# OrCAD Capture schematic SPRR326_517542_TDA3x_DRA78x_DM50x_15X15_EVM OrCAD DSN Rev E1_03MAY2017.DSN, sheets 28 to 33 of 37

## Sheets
28 SH36 - TOOL HPC: size C; rev: A
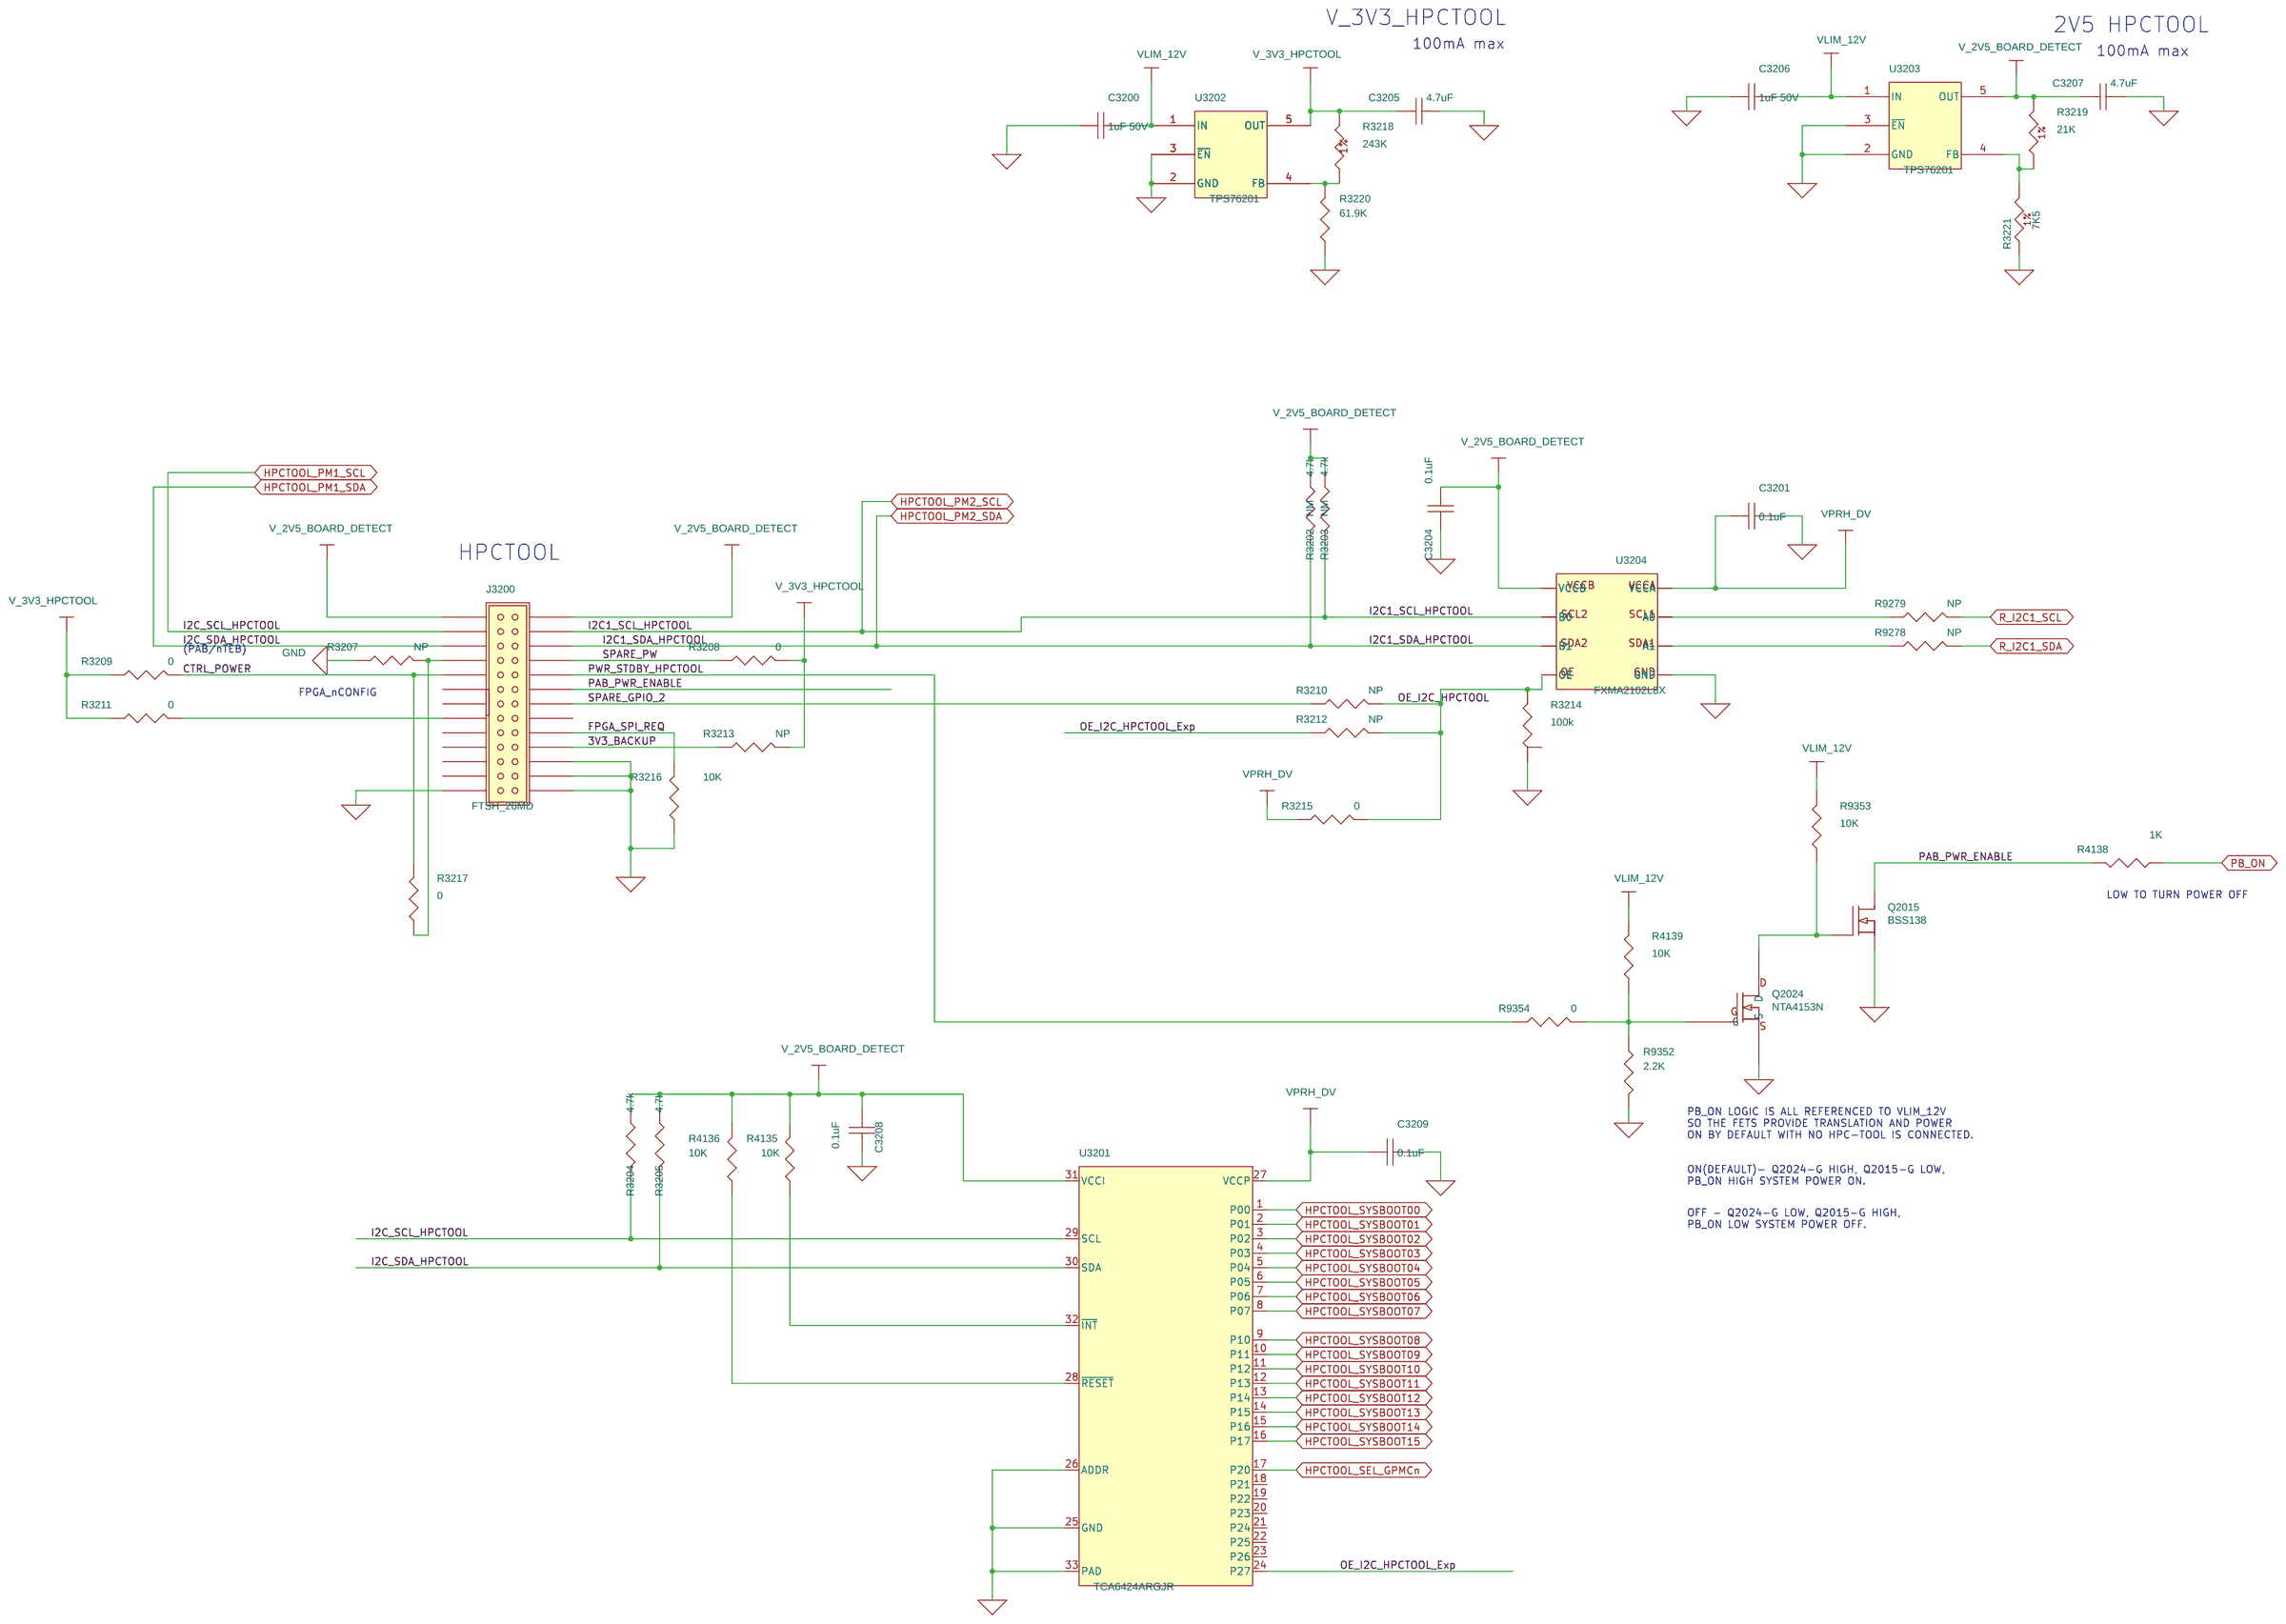
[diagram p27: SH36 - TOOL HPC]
29 SH37 - TOOL POWER MONITOR: size C; rev: E
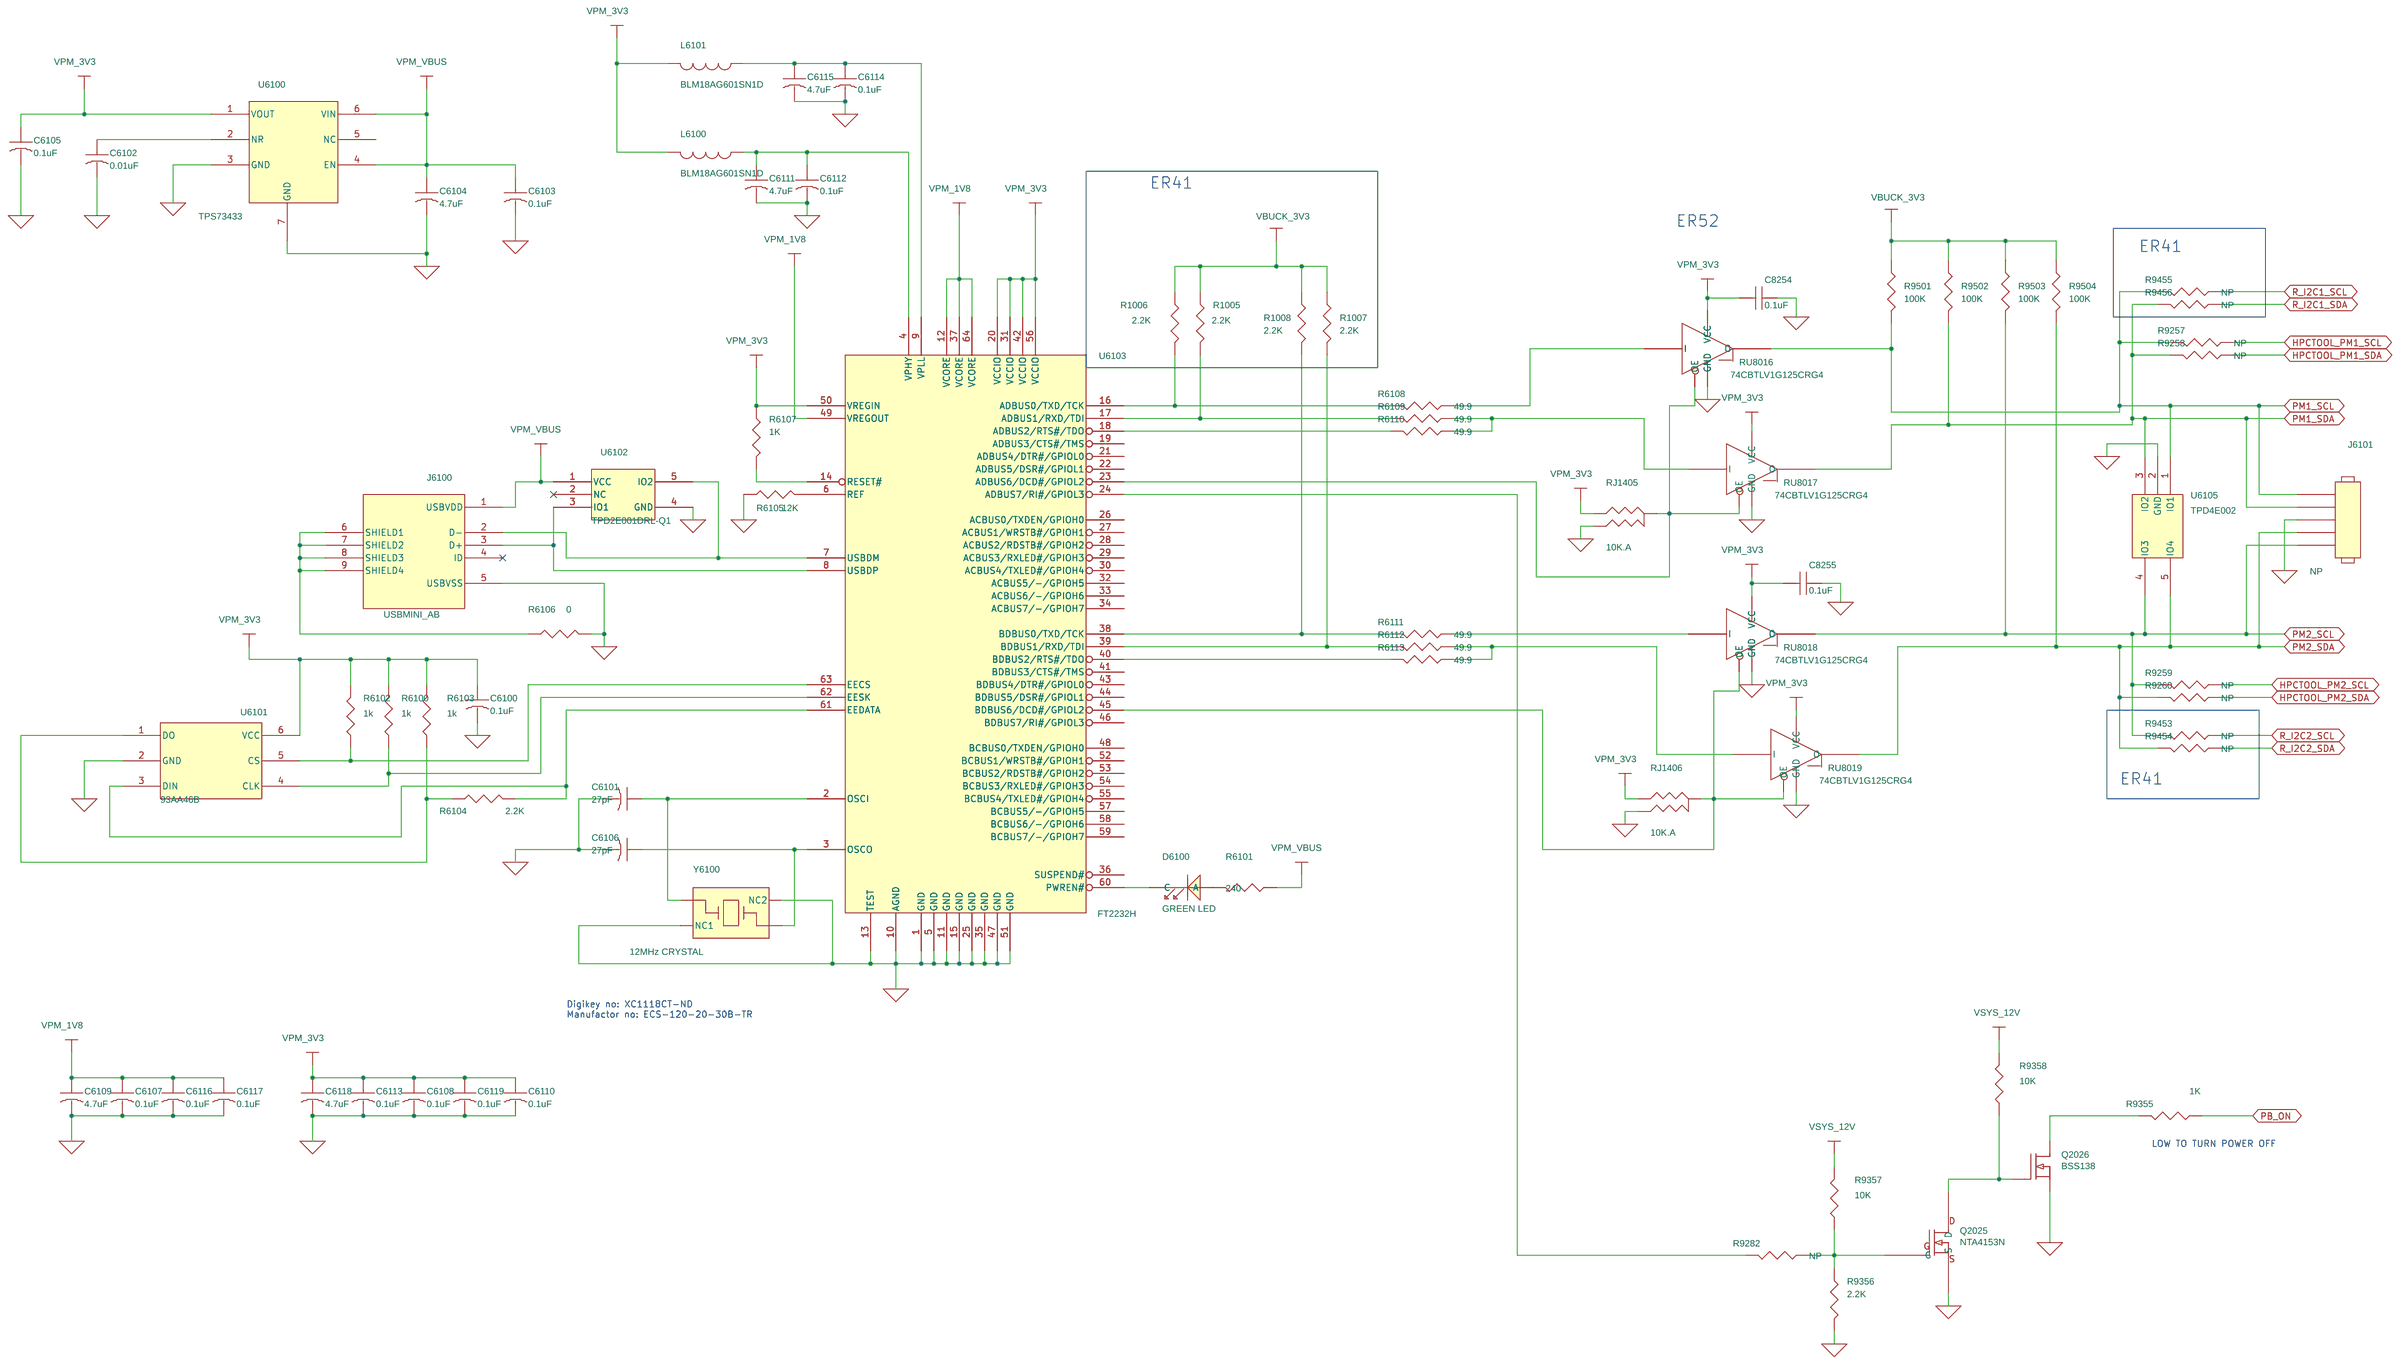
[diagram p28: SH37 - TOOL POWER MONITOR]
30 SH11 - MUX A/B/C: size C; rev: A
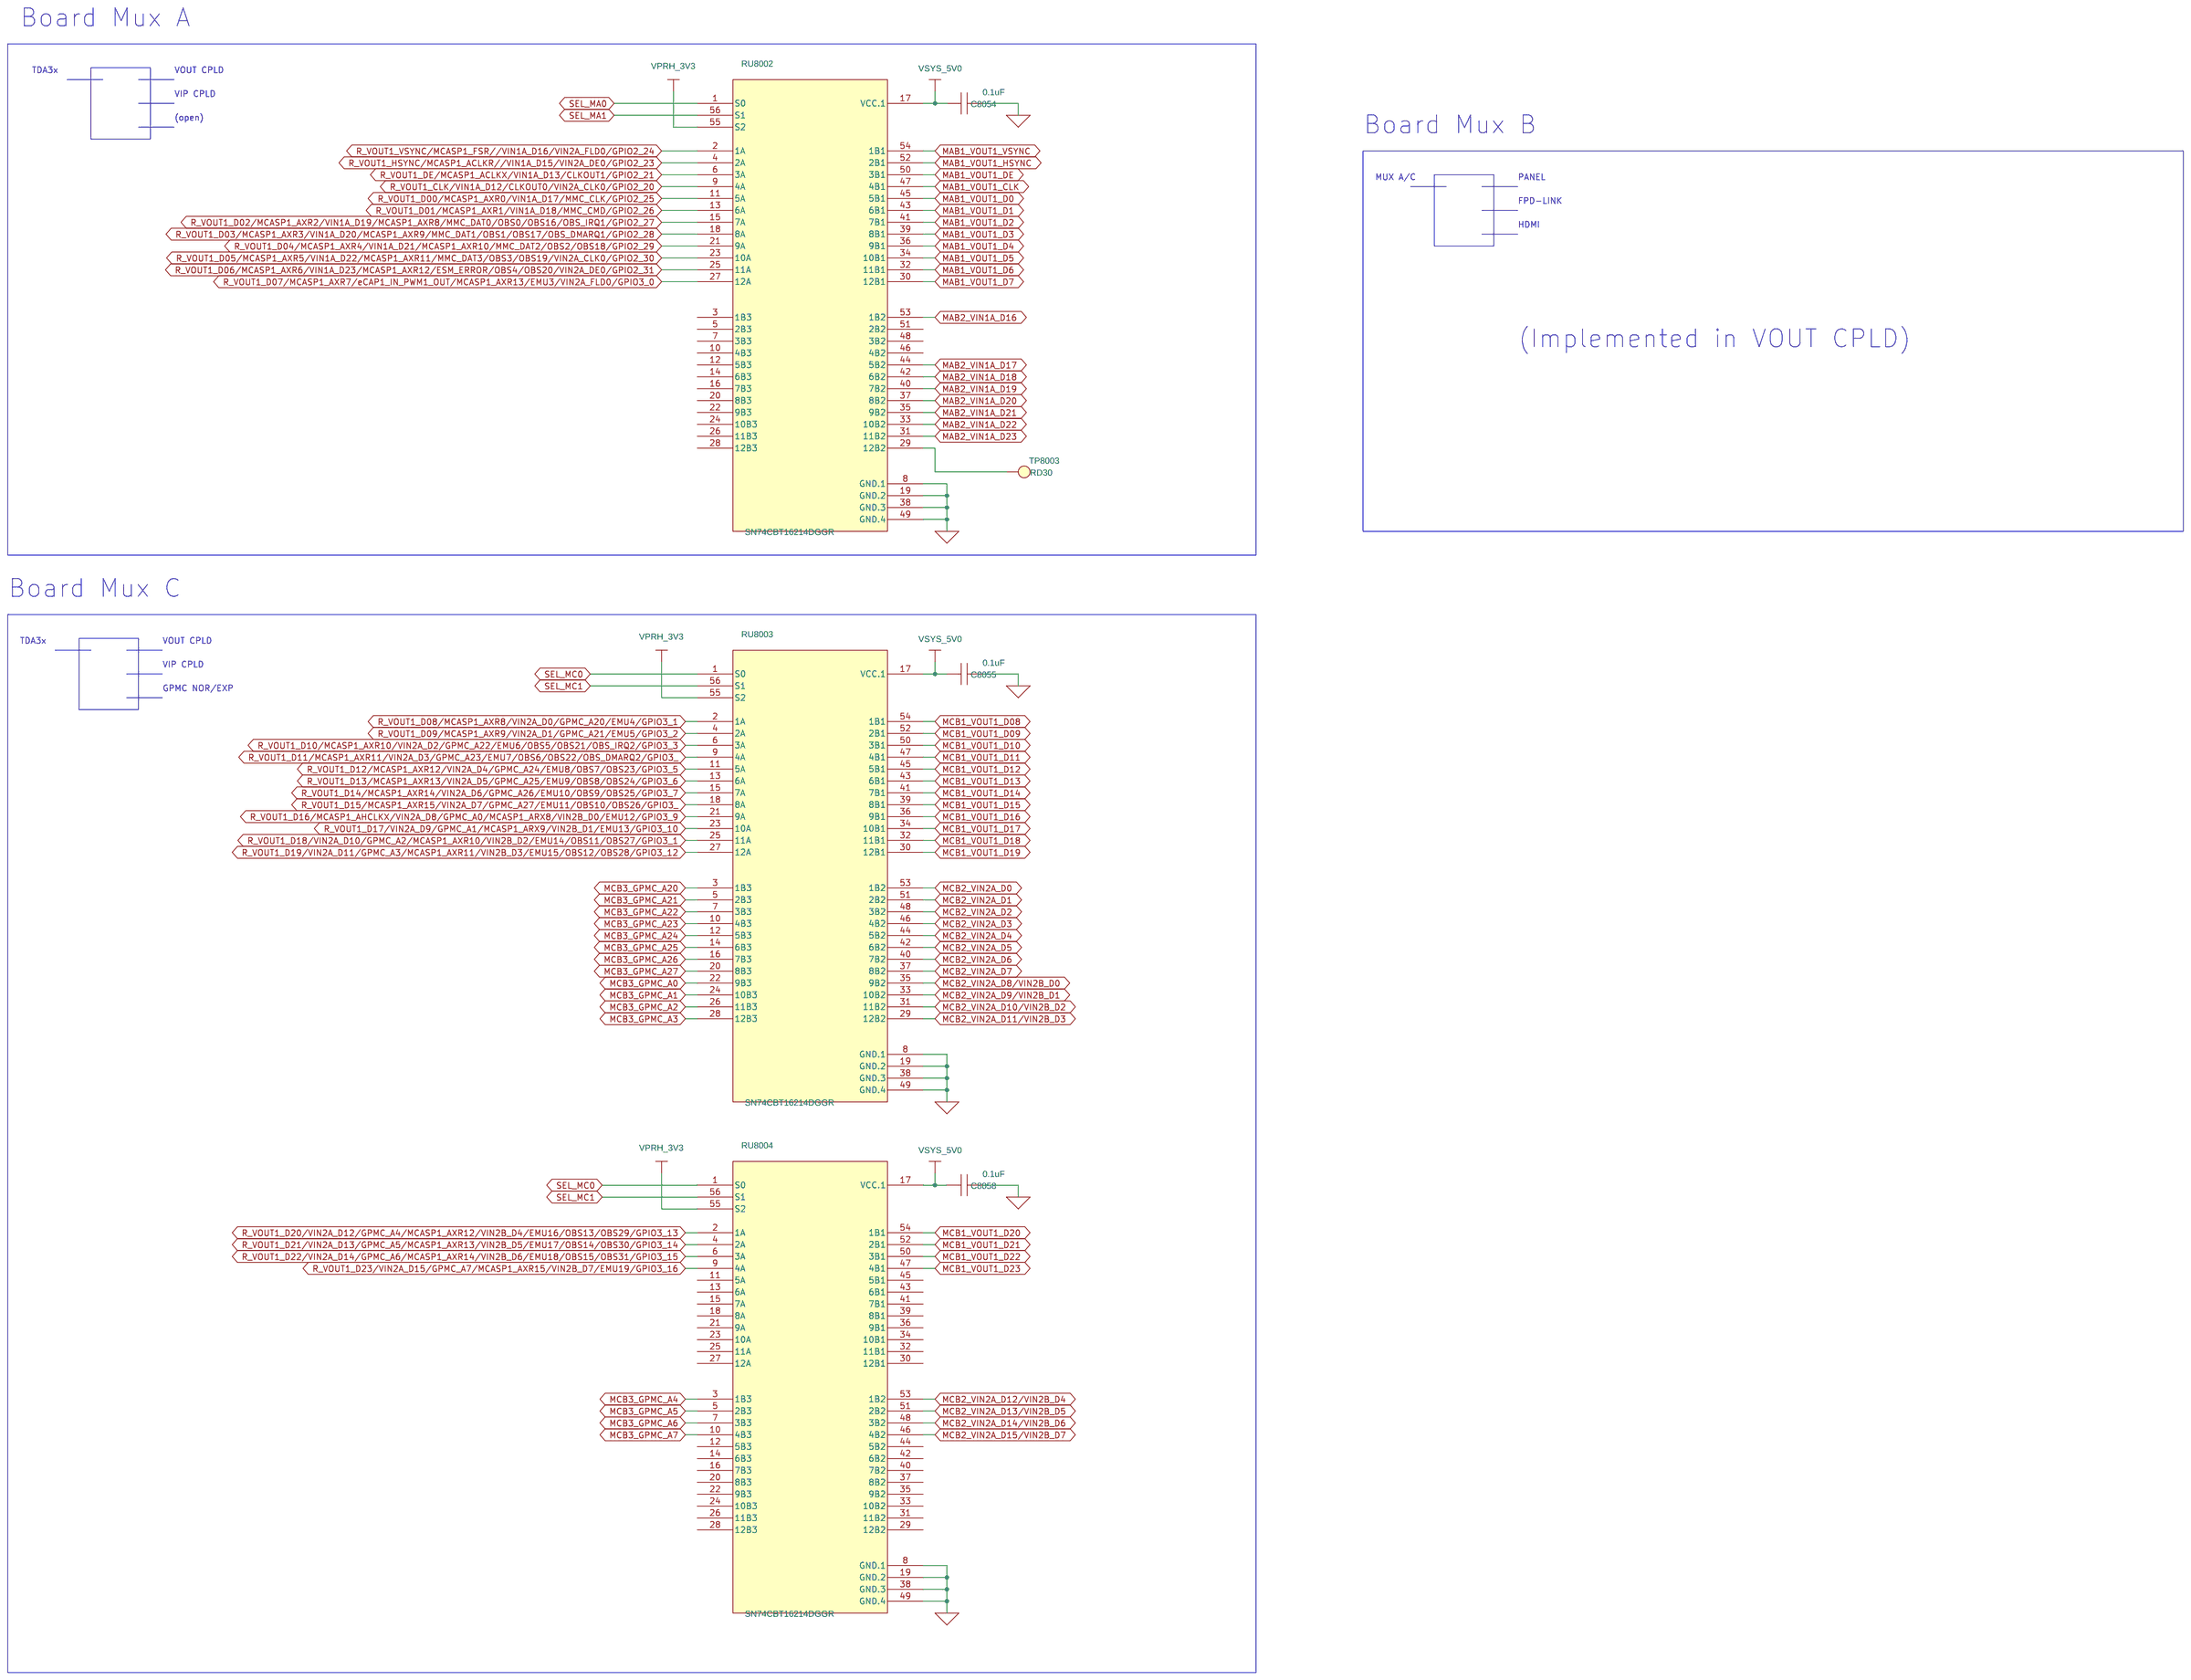
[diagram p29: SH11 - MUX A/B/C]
31 SH09 - BOOT/JTAG: size C; rev: D
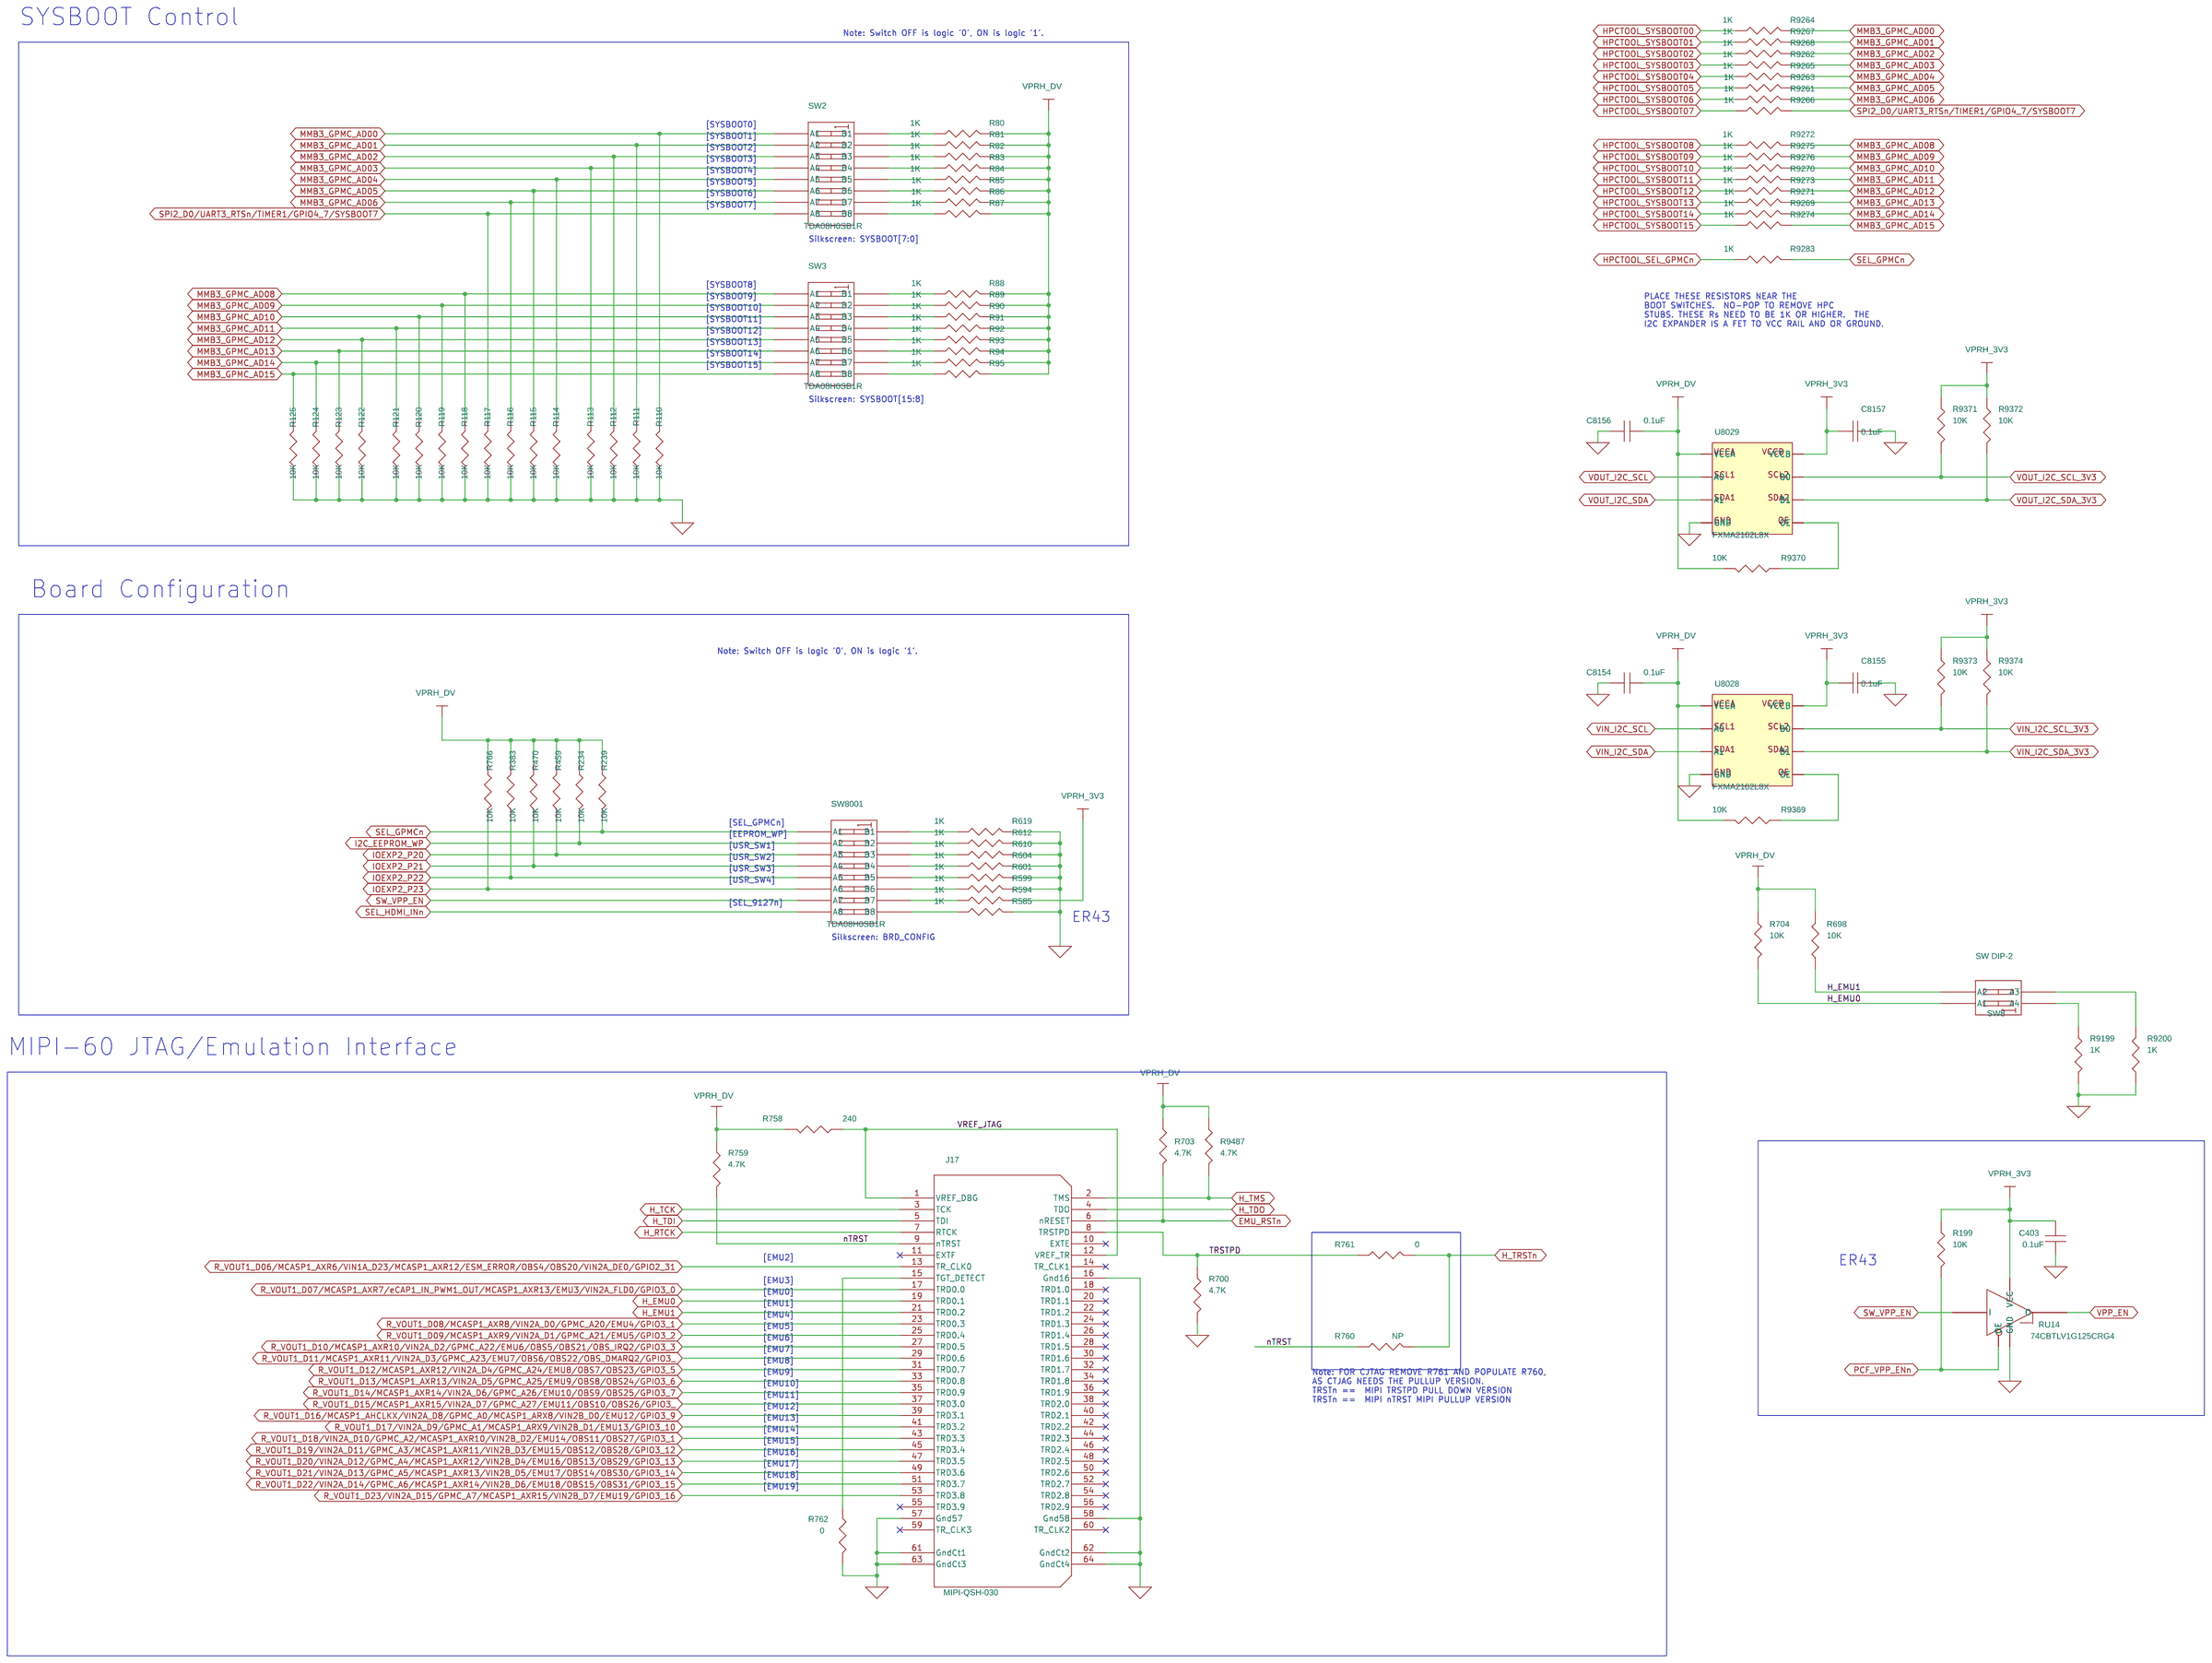
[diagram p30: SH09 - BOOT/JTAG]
32 SH13 - MUX J/K/M/N: size C; rev: B
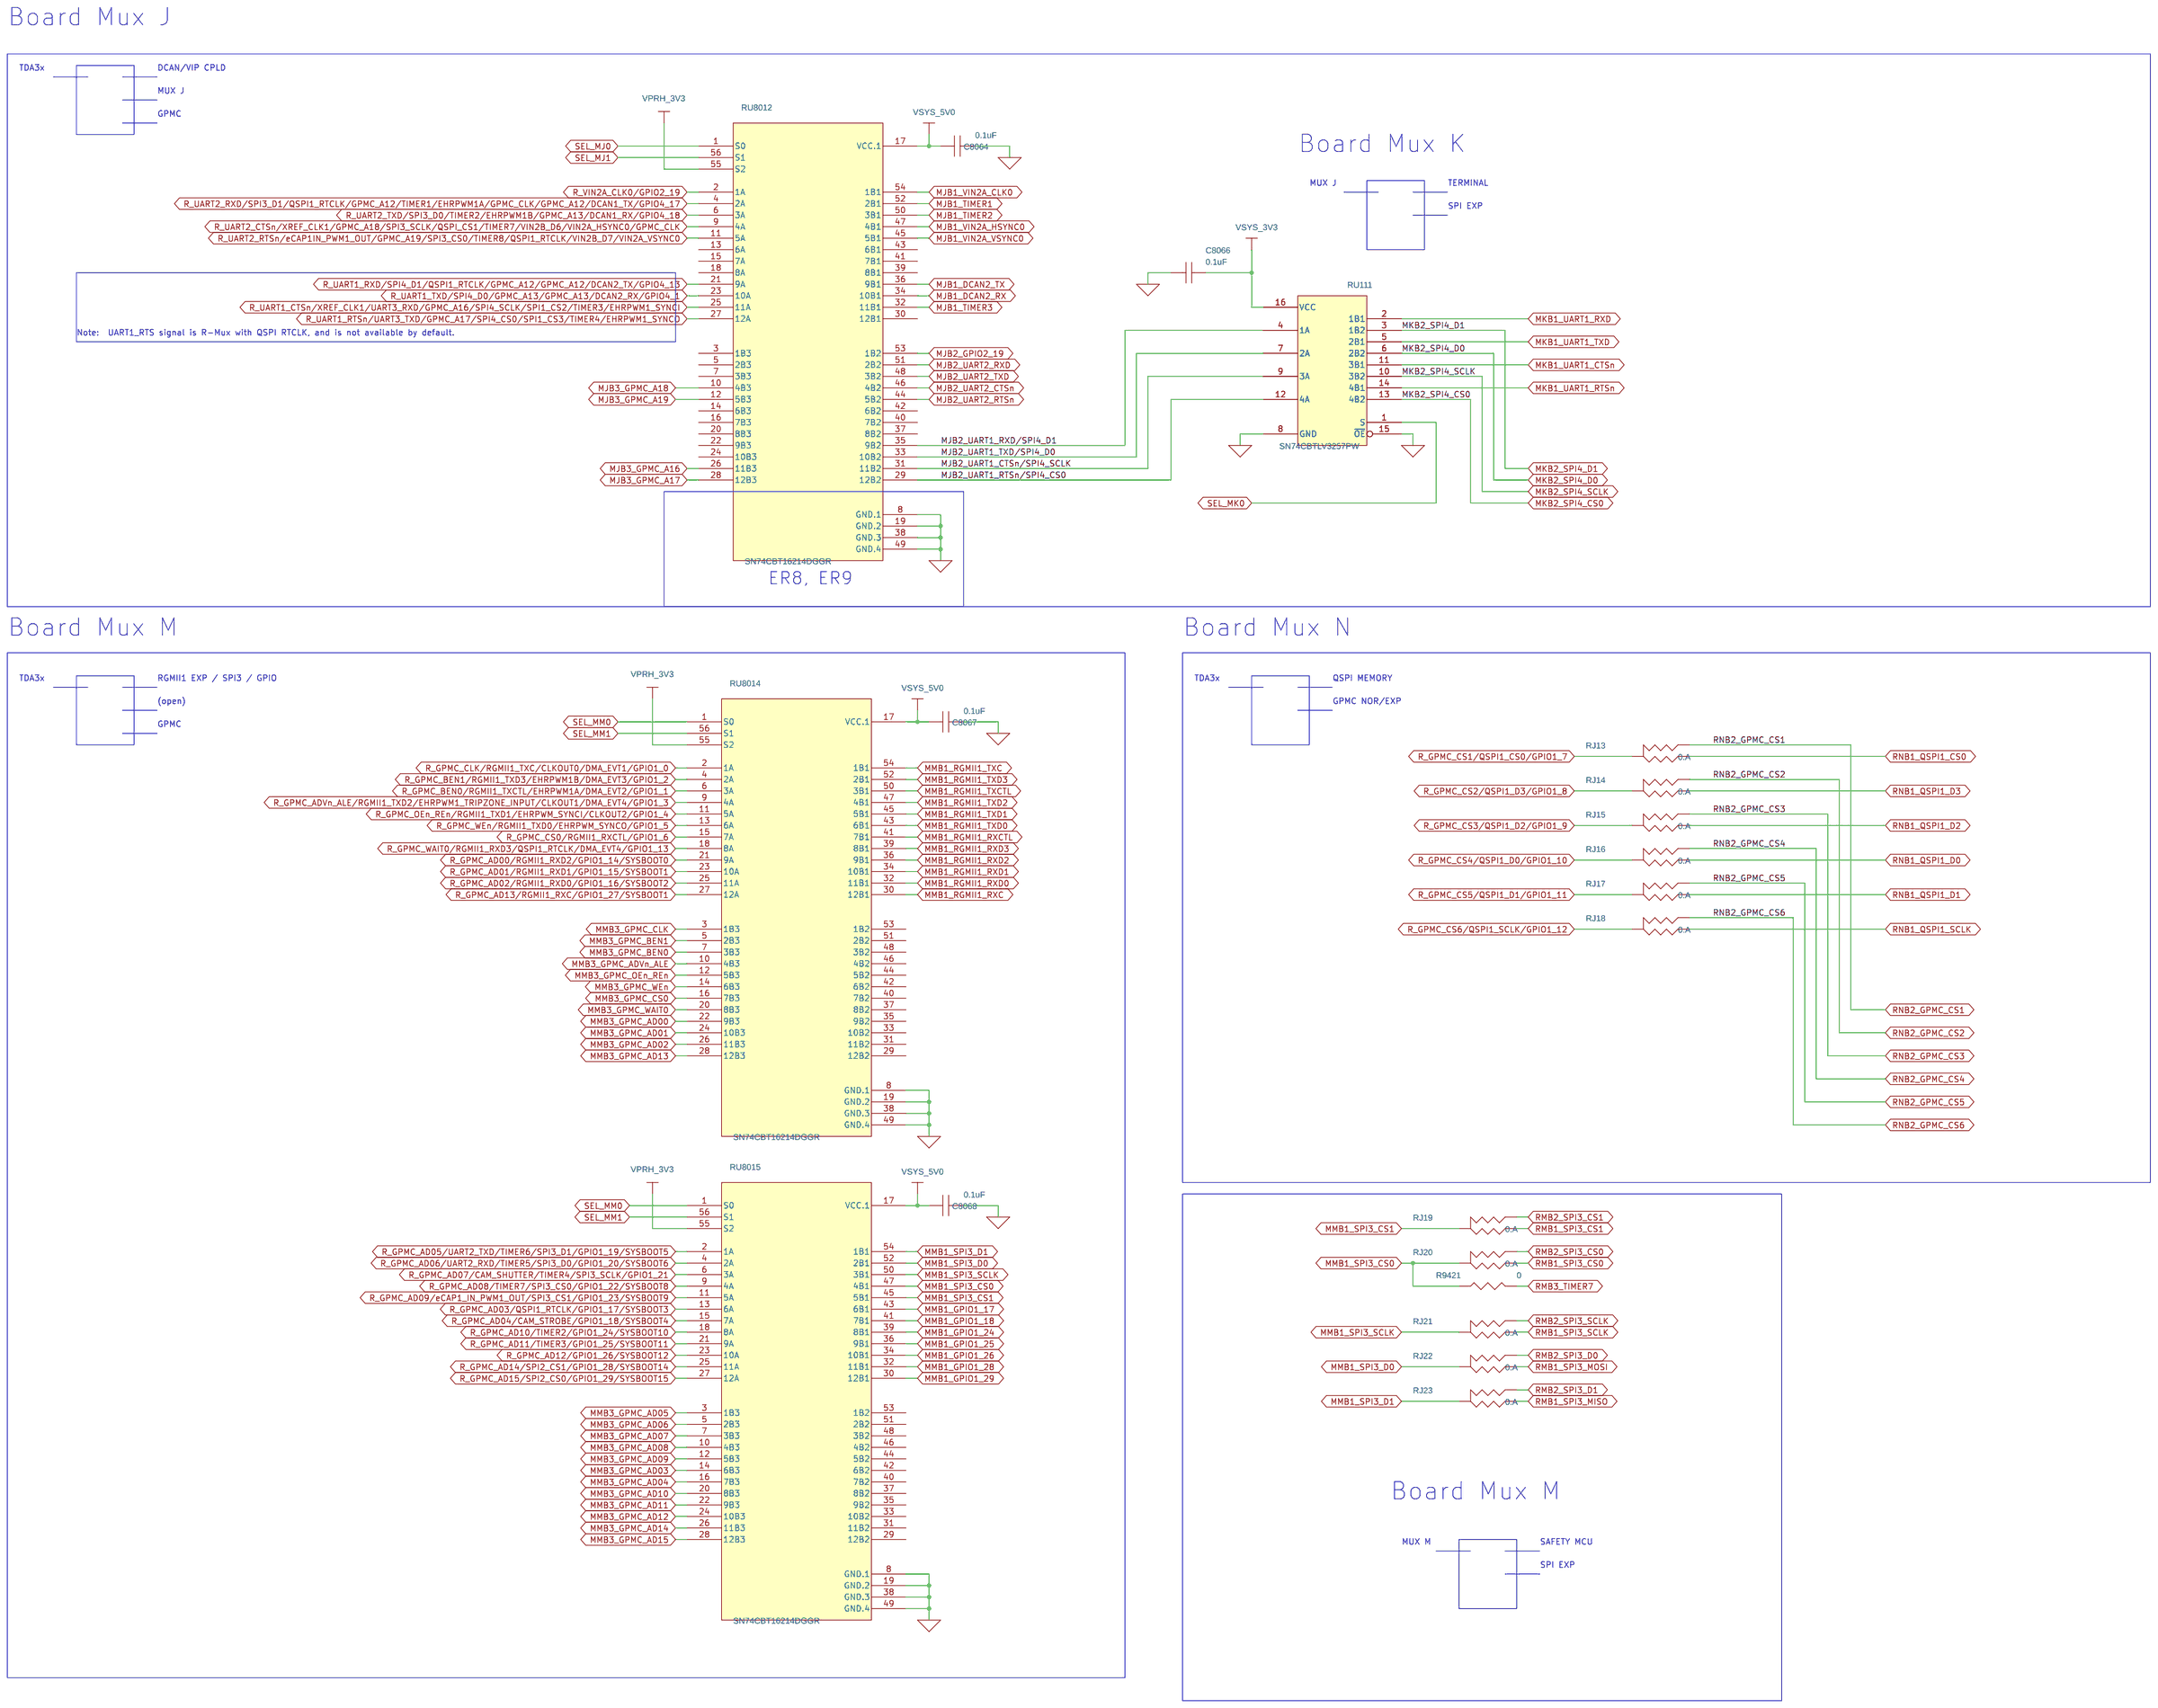
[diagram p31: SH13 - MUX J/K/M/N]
33 SH03 - MAPPING/NOTES: size C; rev: B
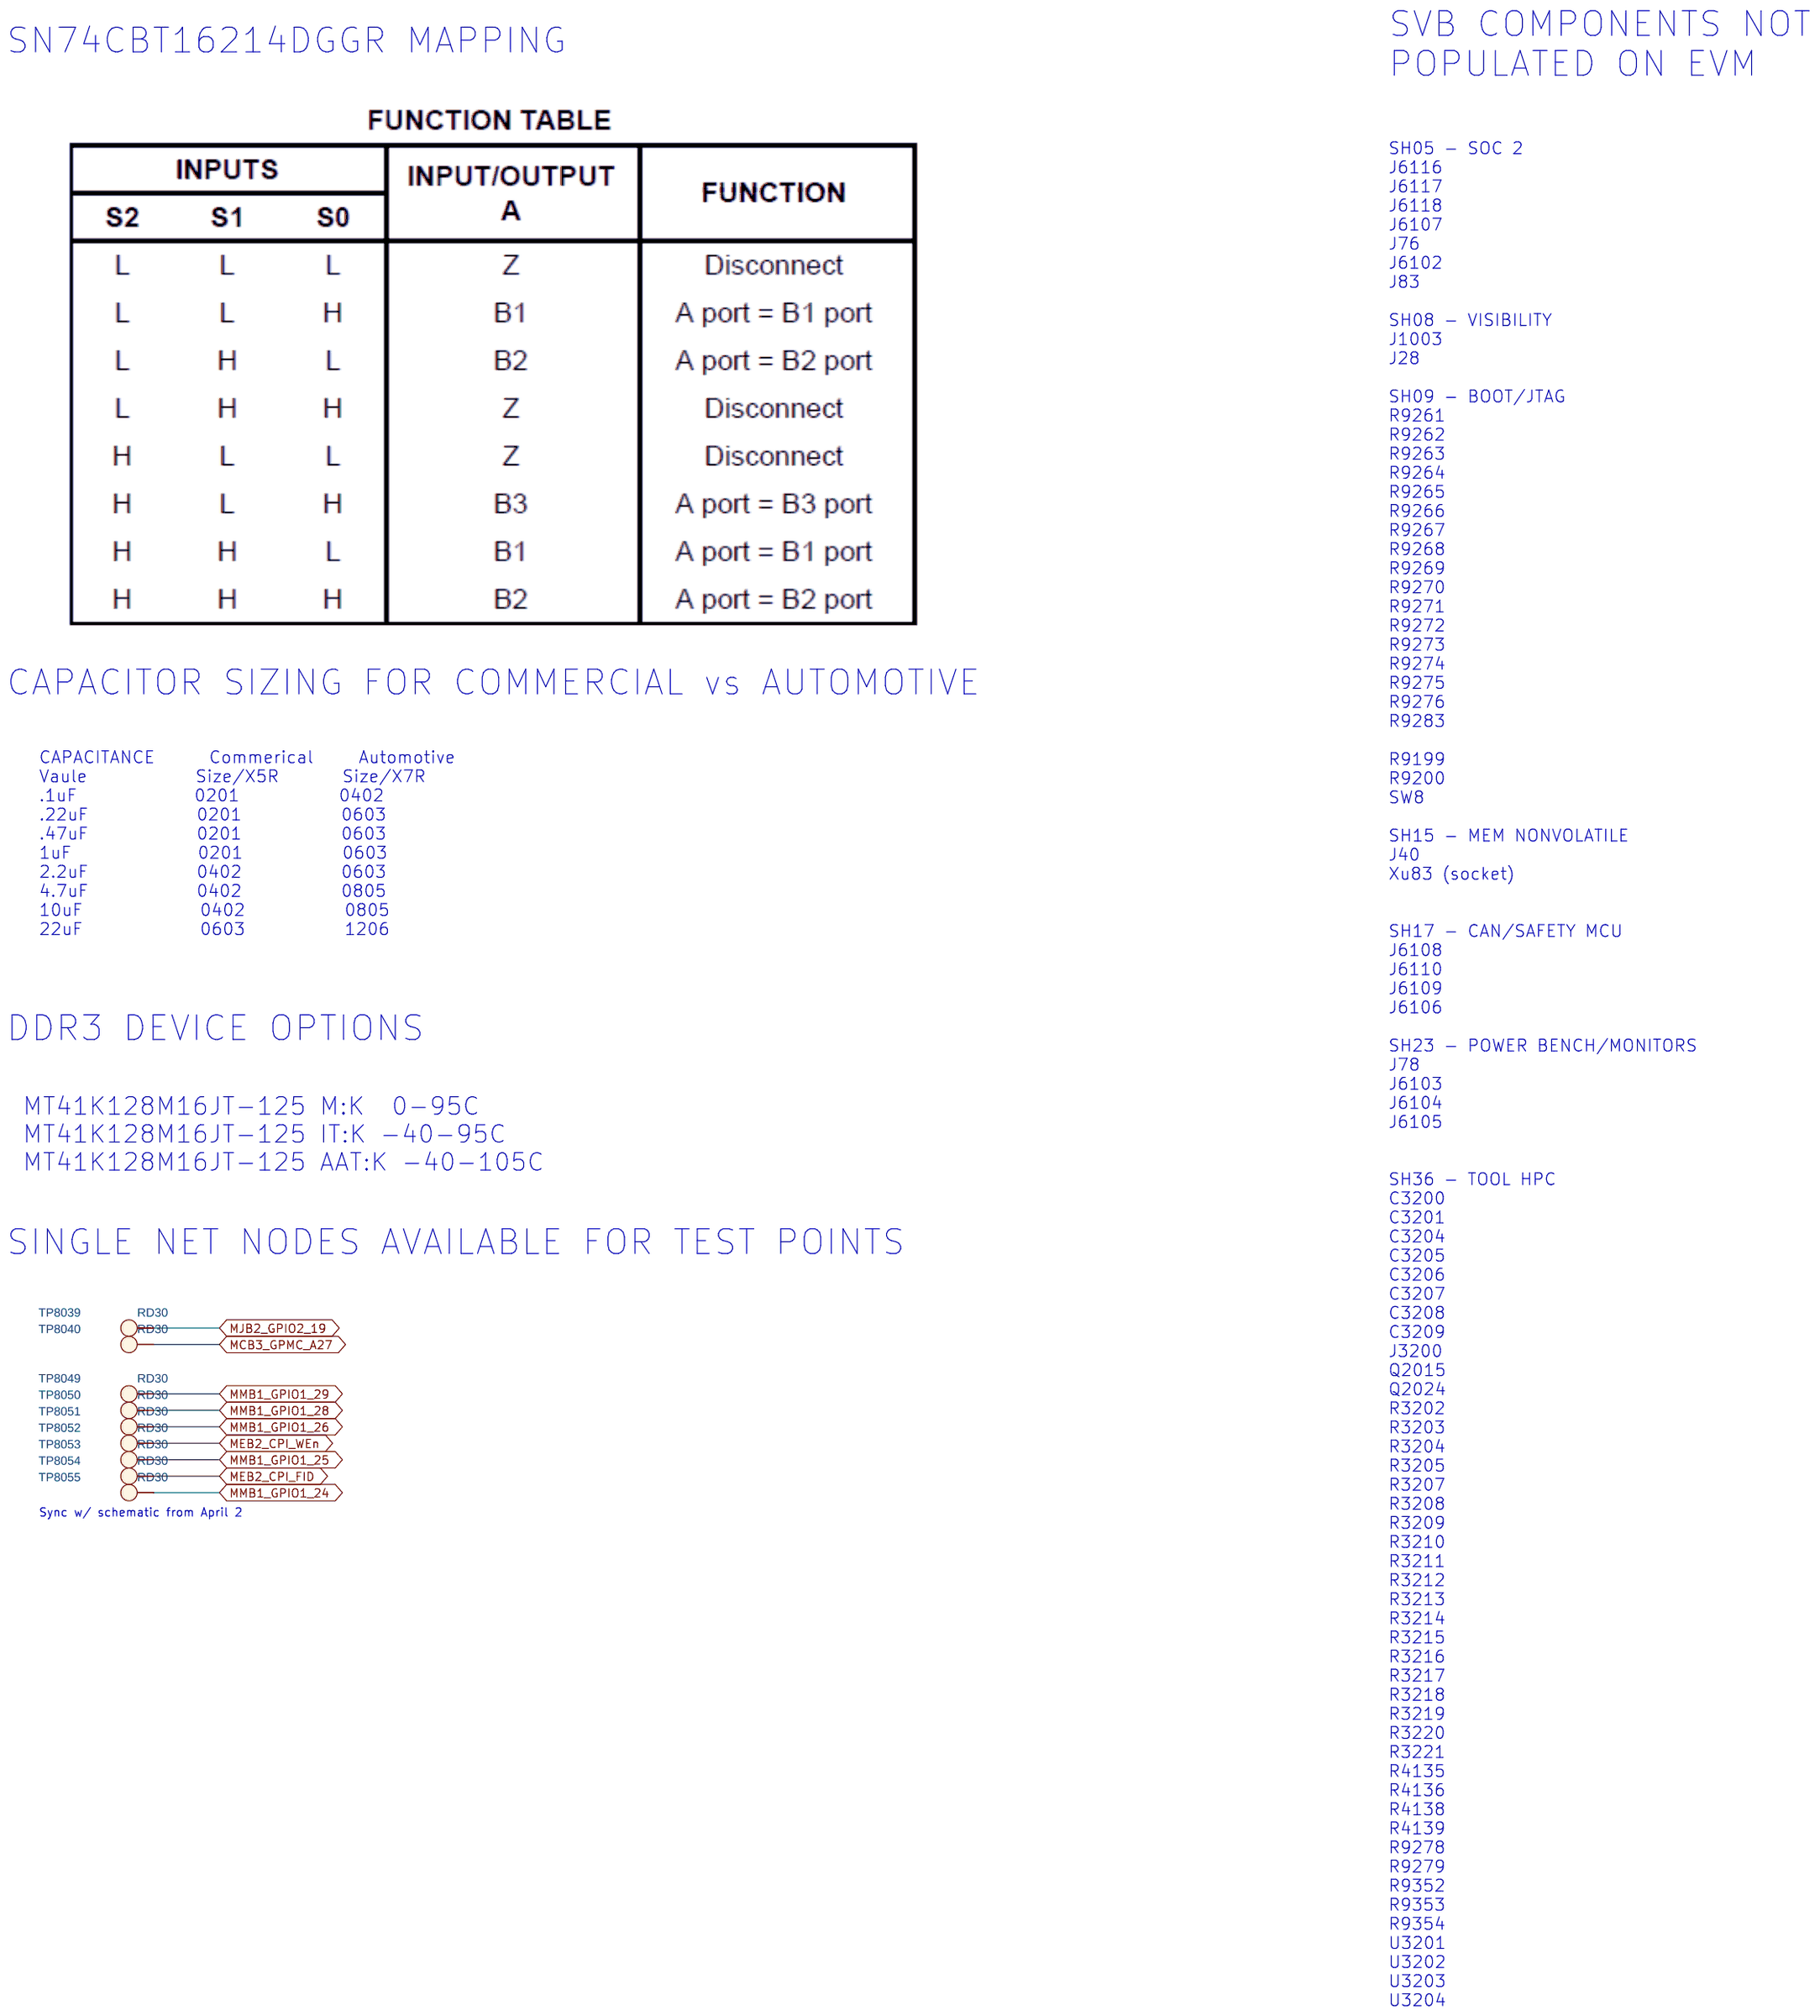
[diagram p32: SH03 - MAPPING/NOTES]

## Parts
sheet SH03 - MAPPING/NOTES
TP8039  RD30  [tp-30RD13]
TP8040  RD30  [tp-30RD13]
TP8049  RD30  [tp-30RD13]
TP8050  RD30  [tp-30RD13]
TP8051  RD30  [tp-30RD13]
TP8052  RD30  [tp-30RD13]
TP8053  RD30  [tp-30RD13]
TP8054  RD30  [tp-30RD13]
TP8055  RD30  [tp-30RD13]
sheet SH09 - BOOT/JTAG
C403  0.1uF  [c402-25]
C8154  0.1uF  [c402-25]
C8155  0.1uF  [c402-25]
C8156  0.1uF  [c402-25]
C8157  0.1uF  [c402-25]
J17  MIPI-QSH-030  [qsh-030-01-f]
R80  1K  [r402-25]
R81  1K  [r402-25]
R82  1K  [r402-25]
R83  1K  [r402-25]
R84  1K  [r402-25]
R85  1K  [r402-25]
R86  1K  [r402-25]
R87  1K  [r402-25]
R88  1K  [r402-25]
R89  1K  [r402-25]
R90  1K  [r402-25]
R91  1K  [r402-25]
R92  1K  [r402-25]
R93  1K  [r402-25]
R94  1K  [r402-25]
R95  1K  [r402-25]
R110  10K  [r402-25]
R111  10K  [r402-25]
R112  10K  [r402-25]
R113  10K  [r402-25]
R114  10K  [r402-25]
R115  10K  [r402-25]
R116  10K  [r402-25]
R117  10K  [r402-25]
R118  10K  [r402-25]
R119  10K  [r402-25]
R120  10K  [r402-25]
R121  10K  [r402-25]
R122  10K  [r402-25]
R123  10K  [r402-25]
R124  10K  [r402-25]
R125  10K  [r402-25]
R199  10K  [r402-25]
R234  10K  [r402-25]
R239  10K  [r402-25]
R383  10K  [r402-25]
R459  10K  [r402-25]
R470  10K  [r402-25]
R585  1K  [r402-25]
R594  1K  [r402-25]
R599  1K  [r402-25]
R601  1K  [r402-25]
R604  1K  [r402-25]
R610  1K  [r402-25]
R612  1K  [r402-25]
R619  1K  [r402-25]
R698  10K  [r402-25]
R700  4.7K  [r402-25]
R703  4.7K  [r402-25]
R704  10K  [r402-25]
R758  240  [r402-25]
R759  4.7K  [r402-25]
R760  NP  [r402-25]
R761  0  [r402-25]
R762  0  [r402-25]
R766  10K  [r402-25]
R9199  1K  [r402-25]
R9200  1K  [r402-25]
R9261  1K  [r402-25]
R9262  1K  [r402-25]
R9263  1K  [r402-25]
R9264  1K  [r402-25]
R9265  1K  [r402-25]
R9266  1K  [r402-25]
R9267  1K  [r402-25]
R9268  1K  [r402-25]
R9269  1K  [r402-25]
R9270  1K  [r402-25]
R9271  1K  [r402-25]
R9272  1K  [r402-25]
R9273  1K  [r402-25]
R9274  1K  [r402-25]
R9275  1K  [r402-25]
R9276  1K  [r402-25]
R9283  1K  [r402-25]
R9369  10K  [r402-25]
R9370  10K  [r402-25]
R9371  10K  [r402-25]
R9372  10K  [r402-25]
R9373  10K  [r402-25]
R9374  10K  [r402-25]
R9487  4.7K  [r402-25]
RU14  74CBTLV1G125CRG4  [dck-5]
SW2  TDA08H0SB1R  [SW8-30X50]
SW3  TDA08H0SB1R  [SW8-30X50]
SW8  SW DIP-2  [sw2-30x50-tda]
SW8001  TDA08H0SB1R  [SW8-30X50]
U8028  FXMA2102L8X  [micropak8]
U8029  FXMA2102L8X  [micropak8]
sheet SH11 - MUX A/B/C
C8054  0.1uF  [c402-25]
C8055  0.1uF  [c402-25]
C8058  0.1uF  [c402-25]
RU8002  SN74CBT16214DGGR  [dgg56-12x80]
RU8003  SN74CBT16214DGGR  [dgg56-12x80]
RU8004  SN74CBT16214DGGR  [dgg56-12x80]
TP8003  RD30  [tp-30RD13]
sheet SH13 - MUX J/K/M/N
C8064  0.1uF  [c402-25]
C8066  0.1uF  [c402-25]
C8067  0.1uF  [c402-25]
C8068  0.1uF  [c402-25]
R9421  0  [r402-25]
RJ13  0.A  [JMP402-25]
RJ14  0.A  [JMP402-25]
RJ15  0.A  [JMP402-25]
RJ16  0.A  [JMP402-25]
RJ17  0.A  [JMP402-25]
RJ18  0.A  [JMP402-25]
RJ19  0.A  [JMP402-25]
RJ20  0.A  [JMP402-25]
RJ21  0.A  [JMP402-25]
RJ22  0.A  [JMP402-25]
RJ23  0.A  [JMP402-25]
RU111  SN74CBTLV3257PW  [tssop16-14x70]
RU8012  SN74CBT16214DGGR  [dgg56-12x80]
RU8014  SN74CBT16214DGGR  [dgg56-12x80]
RU8015  SN74CBT16214DGGR  [dgg56-12x80]
sheet SH36 - TOOL HPC
C3200  1uF 50V  [c805-35x60]
C3201  0.1uF  [c402-25]
C3204  0.1uF  [c402-25]
C3205  4.7uF  [C805-35X60]
C3206  1uF 50V  [c805-35x60]
C3207  4.7uF  [C805-35X60]
C3208  0.1uF  [c402-25]
C3209  0.1uF  [c402-25]
J3200  FTSH_26MD  [TI-JMS_FTSH-2x13PTS_03]
Q2015  BSS138  [SOT23-28X44-GSD]
Q2024  NTA4153N  [SC-75]
R3202  4.7k  [r402-25]
R3203  4.7k  [r402-25]
R3204  4.7k  [r402-25]
R3205  4.7k  [r402-25]
R3207  NP  [r402-25]
R3208  0  [r402-25]
R3209  0  [r402-25]
R3210  NP  [r402-25]
R3211  0  [r402-25]
R3212  NP  [r402-25]
R3213  NP  [r402-25]
R3214  100k  [r402-25]
R3215  0  [r402-25]
R3216  10K  [r402-25]
R3217  0  [r402-25]
R3218  243K  [r603-35X45]
R3219  21K  [r603-35X45]
R3220  61.9K  [r603-35X45]
R3221  7K5  [r603-35X45]
R4135  10K  [r402-25]
R4136  10K  [r402-25]
R4138  1K  [r402-25]
R4139  10K  [r402-25]
R9278  NP  [r402-25]
R9279  NP  [r402-25]
R9352  2.2K  [r402-25]
R9353  10K  [r402-25]
R9354  0  [r402-25]
U3201  TCA6424ARGJR  [cis_pvqfn-n32_01]
U3202  TPS76201  [dbv-20x60-5]
U3203  TPS76201  [dbv-20x60-5]
U3204  FXMA2102L8X  [micropak8]
sheet SH37 - TOOL POWER MONITOR
C6100  0.1uF  [c402-25]
C6101  27pF  [c402-25]
C6102  0.01uF  [c402-25]
C6103  0.1uF  [c402-25]
C6104  4.7uF  [C805-35X60]
C6105  0.1uF  [c402-25]
C6106  27pF  [c402-25]
C6107  0.1uF  [c402-25]
C6108  0.1uF  [c402-25]
C6109  4.7uF  [C805-35X60]
C6110  0.1uF  [c402-25]
C6111  4.7uF  [C805-35X60]
C6112  0.1uF  [c402-25]
C6113  0.1uF  [c402-25]
C6114  0.1uF  [c402-25]
C6115  4.7uF  [C805-35X60]
C6116  0.1uF  [c402-25]
C6117  0.1uF  [c402-25]
C6118  4.7uF  [C805-35X60]
C6119  0.1uF  [c402-25]
C8254  0.1uF  [c402-25]
C8255  0.1uF  [c402-25]
D6100  GREEN LED  [led603-35x45-rev]
J6100  USBMINI_AB  [SAMTEC-MUSB]
J6101  NP  [JUMP1X5-6040]
L6100  BLM18AG601SN1D  [l603-35x45]
L6101  BLM18AG601SN1D  [l603-35x45]
Q2025  NTA4153N  [SC-75]
Q2026  BSS138  [SOT23-28X44-GSD]
R1005  2.2K  [r402-25]
R1006  2.2K  [r402-25]
R1007  2.2K  [r402-25]
R1008  2.2K  [r402-25]
R6100  1k  [r402-25]
R6101  240  [r402-25]
R6102  1k  [r402-25]
R6103  1k  [r402-25]
R6104  2.2K  [r402-25]
R6105  12K  [r402-25]
R6106  0  [r402-25]
R6107  1K  [r402-25]
R6108  49.9  [r402-25]
R6109  49.9  [r402-25]
R6110  49.9  [r402-25]
R6111  49.9  [r402-25]
R6112  49.9  [r402-25]
R6113  49.9  [r402-25]
R9257  NP  [r402-25]
R9258  NP  [r402-25]
R9259  NP  [r402-25]
R9260  NP  [r402-25]
R9282  NP  [r402-25]
R9355  1K  [r402-25]
R9356  2.2K  [r402-25]
R9357  10K  [r402-25]
R9358  10K  [r402-25]
R9453  NP  [r402-25]
R9454  NP  [r402-25]
R9455  NP  [r402-25]
R9456  NP  [r402-25]
R9501  100K  [r402-25]
R9502  100K  [r402-25]
R9503  100K  [r402-25]
R9504  100K  [r402-25]
RJ1405  10K.A  [JMP402-25]
RJ1406  10K.A  [JMP402-25]
RU8016  74CBTLV1G125CRG4  [dck-5]
RU8017  74CBTLV1G125CRG4  [dck-5]
RU8018  74CBTLV1G125CRG4  [dck-5]
RU8019  74CBTLV1G125CRG4  [dck-5]
U6100  TPS73433  [drv6-12x30]
U6101  93AA46B  [DBV6-27X39-6]
U6102  TPD2E001DRL-Q1  [drl5-12x40]
U6103  FT2232H  [PQFP64PM]
U6105  TPD4E002  [drl5-12x40]
Y6100  12MHz CRYSTAL  [xtal4-63x50-ecx53b]

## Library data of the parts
TP8003 TP8039 TP8040 TP8049-TP8055 = TESTPOINT: Part #: TP-30RD13-NO-POP
C403 C8054 C8055 C8058 C8064 C8066-C8068 C8254 C8255 = CAP_NP: Part #: 104446-1100R
C8154 C8156 = CAP_.1_uF_10%_0603: Part #: 104446-1100R
C3201 C3204 C3208 C3209 C8155 C8157 = X5R_100nF_6V3: Part #: 104446-1100R
J17 = MIPI-QTH-030_1: Part #: 101884-0030R
R80-R95 R585 R594 R599 R601 R604 R610 R612 R619 R9261-R9276 R9283 = R_1: Part #: 101370-1002R
R110-R125 = R_1: Part #: 101370-1003R
R199 R234 R239 R383 R459 R470 R698 R704 R766 R9369-R9374 = R: Part #: 101370-1003R
R700 R703 R759 R9487 = R: Part #: 102145-4702R
R758 R6101 = R: Part #: 102145-2401R
R760 R9257-R9260 R9282 R9453-R9456 = R: Part #: R0402-NOPOP
R761 R762 R6106 R9421 = R: Part #: 101370-0001R
R6100 R6102 R6103 R6107 R9199 R9200 = R: Part #: 101370-1002R
RU14 RU8016-RU8019 = SN74LVC1G125_0: Part #: 101689-0125R
SW2 SW3 SW8001 = SW_DIP-8: Part #: 101184-0008R
SW8 = SW_DIP-2: Part #: 101184-0002R
U3204 U8028 U8029 = FXMA2102UMX_0: GPAO_ART: 05600047080AA; Part #: 104458-0001R
RU8002-RU8004 RU8012 RU8014 RU8015 = SN74CBT16214DGGR_0: Part #: 102513-0001R
RJ13-RJ23 = RJUMP3: Part #: 101370-0001R
RU111 = SN74CBT3257PW: Part #: 101670-0001R
C3200 C3206 = X5R_001uF_10V: Part #: 100201-0100R
C3205 C3207 = X5R_04.7uF_6.3V: Part #: 101063-0470R
J3200 = FTSH-113-01-L-DV-K: Part #: 104277-0013R
Q2015 Q2026 = MOSFET_N_1_v2: Part #: 100680-0001R
Q2024 Q2025 = NTA4153N: Part #: 102437-0001R
R3202 R3203 = 0402_5%_004.7K: ASSEMBLY: NM; Part #: 102145-4702R
R3204 R3205 = 0402_5%_004.7K: Part #: 102145-4702R
R3207 = 0402_5%_000_chevron: Part #: R0402-NOPOP
R3208 R3209 R3211 R3215 R3217 R9354 = 0402_5%_000_chevron: Part #: 101370-0001R
R3210 R3212 R3213 R9278 R9279 = 0402_5%_000_chevron: ASSEMBLY: NM; Part #: R0402-NOPOP
R3214 = 0201_5%_100k: Part #: 101370-1004R
R3216 R4135 R4136 = 0402_1%_010k: Part #: 101370-1003R
R3218 = 0805_1%_249K: Part #: 100642-2434R
R3219 = 0603_1%_021K: Part #: 100642-2103R
R3220 = 0603_5%_062K: Part #: 100642-6193R
R3221 = 0603_1%_007.5K: Part #: 100642-7502R
R4138 R9355 = R_2: Part #: 101370-1002R
R4139 R9353 R9357 R9358 = RESISTOR: Part #: 101370-1003R
R1005-R1008 R6104 R9352 R9356 = R: Part #: 101370-2202R
U3201 = TCA6424A: Part #: 104230-0001R
U3202 U3203 = LDO_TPS76201_ADJ_100mA: Part #: 104459-0001R
C6100 C6103 C6105 C6107 C6108 C6110 C6112-C6114 C6116 C6117 C6119 = CAP: Part #: 104446-1100R
C6101 C6106 = CAP: Part #: 101782-1274R
C6102 = CAP: Part #: 101587-1101R
C6104 C6109 C6111 C6115 C6118 = CAP: Part #: 101063-0470R
D6100 = LED_0: Part #: 103557-0001R
J6100 = USBMINI_B_0: Part #: 101956-0001R
J6101 = HEADER_5: Part #: NO-POP
L6100 L6101 = INDUCTOR: Part #: 101858-6001R
R6105 = R: Part #: 102145-1203R
R6108-R6113 = R: Part #: 102145-4990R
R9501-R9504 = R: Part #: 101370-1004R
RJ1405 RJ1406 = RJUMP3: Part #: 101370-1003R
U6100 = TPS73433_1: Part #: 103554-0001R
U6101 = 93C46_3V3: Part #: 103564-0001R
U6102 = TPD2E001_0: Part #: 102728-0001R
U6103 = FT2232H_0: Part #: 103172-0001R
U6105 = TPD4E002: Part #: 103176-0001R
Y6100 = CRYSTAL_9: Part #: 103560-0012R

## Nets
3V3_BACKUP: J3200.20 R3213.1
GND: C403.1 C3200.1 C3201.1 C3204.1 C3205.2 C3206.1 C3207.2 C3208.1 C3209.1 C6100.2 C6101.2 C6102.2 C6103.2 C6104.2 C6105.2 C6106.2 C6107.2 C6108.2 C6109.2 C6110.2 C6111.2 C6112.2 C6113.2 C6114.2 C6115.2 C6116.2 C6117.2 C6118.2 C6119.2 C8054.2 C8055.2 C8058.2 C8064.2 C8066.2 C8067.2 C8068.2 C8154.2 C8155.1 C8156.2 C8157.1 C8254.1 C8255.1 J17.16(Gnd16) J17.57(Gnd57) J17.58(Gnd58) J17.61(GndCt1) J17.62(GndCt2) J17.63(GndCt3) J17.64(GndCt4) J3200.22 J3200.24 J3200.25 J3200.26 J6100.5(USBVSS) J6101.3 Q2015.S Q2024.2(S) Q2025.2(S) Q2026.S R110.2 R111.2 R112.2 R113.2 R114.2 R115.2 R116.2 R117.2 R118.2 R119.2 R120.2 R121.2 R122.2 R123.2 R124.2 R125.2 R585.1 R599.1 R601.1 R604.1 R610.1 R612.1 R619.1 R700.2 R762.1 R3207.1 R3214.1 R3216.1 R3220.1 R3221.1 R6105.1 R6106.2 R9199.2 R9200.2 R9352.2 R9356.2 RJ1405.3 RJ1406.3 RU14.3(GND) RU111.8(GND) RU111.15(~{OE}) RU8002.8(GND.1) RU8002.19(GND.2) RU8002.38(GND.3) RU8002.49(GND.4) RU8003.8(GND.1) RU8003.19(GND.2) RU8003.38(GND.3) RU8003.49(GND.4) RU8004.8(GND.1) RU8004.19(GND.2) RU8004.38(GND.3) RU8004.49(GND.4) RU8012.8(GND.1) RU8012.19(GND.2) RU8012.38(GND.3) RU8012.49(GND.4) RU8014.8(GND.1) RU8014.19(GND.2) RU8014.38(GND.3) RU8014.49(GND.4) RU8015.8(GND.1) RU8015.19(GND.2) RU8015.38(GND.3) RU8015.49(GND.4) RU8016.3(GND) RU8017.3(GND) RU8018.3(GND) RU8019.3(GND) U3201.25(GND) U3201.26(ADDR) U3201.33(PAD) U3202.2(GND) U3202.3(~{EN}) U3203.2(GND) U3203.3(~{EN}) U3204.4(GND) U6100.3(GND) U6100.7(GND) U6101.2(GND) U6102.4(GND) U6103.1(GND) U6103.5(GND) U6103.10(AGND) U6103.11(GND) U6103.13(TEST) U6103.15(GND) U6103.25(GND) U6103.35(GND) U6103.47(GND) U6103.51(GND) U6105.2(GND) U8028.4(GND) U8029.4(GND) Y6100.2(NC1) Y6100.4(NC2) ; also on sheet 4 5 6 7 8 9 10 11 12 13 14 15 16 17 18 19 20 21 22 23 25 26 27 34 35 36 37
MCB2_VIN2A_D8/VIN2B_D0: RU8003.35(9B2) ; also on sheet 27
MCB2_VIN2A_D9/VIN2B_D1: RU8003.33(10B2) ; also on sheet 27
MCB2_VIN2A_D10/VIN2B_D2: RU8003.31(11B2) ; also on sheet 27
MCB2_VIN2A_D11/VIN2B_D3: RU8003.29(12B2) ; also on sheet 27
MCB2_VIN2A_D12/VIN2B_D4: RU8004.53(1B2) ; also on sheet 27
MCB2_VIN2A_D13/VIN2B_D5: RU8004.51(2B2) ; also on sheet 27
MCB2_VIN2A_D14/VIN2B_D6: RU8004.48(3B2) ; also on sheet 27
MCB2_VIN2A_D15/VIN2B_D7: RU8004.46(4B2) ; also on sheet 27
R_UART2_RTSn/eCAP1IN_PWM1_OUT/GPMC_A19/SPI3_CS0/TIMER8/QSPI1_RTCLK/VIN2B_D7/VIN2A_VSYNC0: RU8012.11(5A) ; also on sheet 7
VIN_I2C_SCL: U8028.2(A0) ; also on sheet 7 21 22
VIN_I2C_SCL_3V3: R9373.2 U8028.7(B0) ; also on sheet 19 20 21 23 25
VIN_I2C_SDA: U8028.3(A1) ; also on sheet 7 21 22
VIN_I2C_SDA_3V3: R9374.2 U8028.6(B1) ; also on sheet 19 20 21 23 25
CTRL_POWER: J3200.9 R3209.2 R3217.2
EMU_RSTn: J17.6(nRESET) R703.2 ; also on sheet 13
FPGA_SPI_REQ: J3200.18 R3216.2
H_EMU0: J17.19(TRD0.1) R704.2 SW8.1(A1) ; also on sheet 4
H_EMU1: J17.21(TRD0.2) R698.2 SW8.2(A2) ; also on sheet 4
H_RTCK: J17.7(RTCK) ; also on sheet 4
H_TCK: J17.3(TCK) ; also on sheet 4
H_TDI: J17.5(TDI) ; also on sheet 4
H_TDO: J17.4(TDO) ; also on sheet 4
H_TMS: J17.2(TMS) R9487.2 ; also on sheet 4
H_TRSTn: R760.2 R761.2 ; also on sheet 4
HPCTOOL_PM1_SCL: J3200.3 R3204.1 R9257.1 U3201.29(SCL)
HPCTOOL_PM1_SDA: J3200.5 R3205.1 R9258.1 U3201.30(SDA)
HPCTOOL_PM2_SCL: J3200.4 R3203.1 R9259.1 U3204.7(B0)
HPCTOOL_PM2_SDA: J3200.6 R3202.1 R9260.1 U3204.6(B1)
HPCTOOL_SEL_GPMCn: R9283.2 U3201.17(P20)
HPCTOOL_SYSBOOT00: R9264.2 U3201.1(P00)
HPCTOOL_SYSBOOT01: R9267.2 U3201.2(P01)
HPCTOOL_SYSBOOT02: R9268.2 U3201.3(P02)
HPCTOOL_SYSBOOT03: R9262.2 U3201.4(P03)
HPCTOOL_SYSBOOT04: R9265.2 U3201.5(P04)
HPCTOOL_SYSBOOT05: R9263.2 U3201.6(P05)
HPCTOOL_SYSBOOT06: R9261.2 U3201.7(P06)
HPCTOOL_SYSBOOT07: R9266.2 U3201.8(P07)
HPCTOOL_SYSBOOT08: R9272.2 U3201.9(P10)
HPCTOOL_SYSBOOT09: R9275.2 U3201.10(P11)
HPCTOOL_SYSBOOT10: R9276.2 U3201.11(P12)
HPCTOOL_SYSBOOT11: R9270.2 U3201.12(P13)
HPCTOOL_SYSBOOT12: R9273.2 U3201.13(P14)
HPCTOOL_SYSBOOT13: R9271.2 U3201.14(P15)
HPCTOOL_SYSBOOT14: R9269.2 U3201.15(P16)
HPCTOOL_SYSBOOT15: R9274.2 U3201.16(P17)
I2C_EEPROM_WP: R234.2 SW8001.2(A2) ; also on sheet 36
IOEXP2_P20: R459.2 SW8001.3(A3) ; also on sheet 8 27
IOEXP2_P21: R470.2 SW8001.4(A4) ; also on sheet 8 27
IOEXP2_P22: R383.2 SW8001.5(A5) ; also on sheet 8 26
IOEXP2_P23: R766.2 SW8001.6(A6) ; also on sheet 8 26
LP_INTn: RU8015.41(7B1) ; also on sheet 13
MAB1_VOUT1_CLK: RU8002.47(4B1) ; also on sheet 26
MAB1_VOUT1_D0: RU8002.45(5B1) ; also on sheet 26
MAB1_VOUT1_D1: RU8002.43(6B1) ; also on sheet 26
MAB1_VOUT1_D2: RU8002.41(7B1) ; also on sheet 26
MAB1_VOUT1_D3: RU8002.39(8B1) ; also on sheet 26
MAB1_VOUT1_D4: RU8002.36(9B1) ; also on sheet 26
MAB1_VOUT1_D5: RU8002.34(10B1) ; also on sheet 26
MAB1_VOUT1_D6: RU8002.32(11B1) ; also on sheet 26
MAB1_VOUT1_D7: RU8002.30(12B1) ; also on sheet 26
MAB1_VOUT1_DE: RU8002.50(3B1) ; also on sheet 26
MAB1_VOUT1_HSYNC: RU8002.52(2B1) ; also on sheet 26
MAB1_VOUT1_VSYNC: RU8002.54(1B1) ; also on sheet 26
MAB2_VIN1A_D16: RU8002.53(1B2) ; also on sheet 27
MAB2_VIN1A_D17: RU8002.44(5B2) ; also on sheet 27
MAB2_VIN1A_D18: RU8002.42(6B2) ; also on sheet 27
MAB2_VIN1A_D19: RU8002.40(7B2) ; also on sheet 27
MAB2_VIN1A_D20: RU8002.37(8B2) ; also on sheet 27
MAB2_VIN1A_D21: RU8002.35(9B2) ; also on sheet 27
MAB2_VIN1A_D22: RU8002.33(10B2) ; also on sheet 27
MAB2_VIN1A_D23: RU8002.31(11B2) ; also on sheet 27
MCB1_VOUT1_D08: RU8003.54(1B1) ; also on sheet 26
MCB1_VOUT1_D09: RU8003.52(2B1) ; also on sheet 26
MCB1_VOUT1_D10: RU8003.50(3B1) ; also on sheet 26
MCB1_VOUT1_D11: RU8003.47(4B1) ; also on sheet 26
MCB1_VOUT1_D12: RU8003.45(5B1) ; also on sheet 26
MCB1_VOUT1_D13: RU8003.43(6B1) ; also on sheet 26
MCB1_VOUT1_D14: RU8003.41(7B1) ; also on sheet 26
MCB1_VOUT1_D15: RU8003.39(8B1) ; also on sheet 26
MCB1_VOUT1_D16: RU8003.36(9B1) ; also on sheet 26
MCB1_VOUT1_D17: RU8003.34(10B1) ; also on sheet 26
MCB1_VOUT1_D18: RU8003.32(11B1) ; also on sheet 26
MCB1_VOUT1_D19: RU8003.30(12B1) ; also on sheet 26
MCB1_VOUT1_D20: RU8004.54(1B1) ; also on sheet 26
MCB1_VOUT1_D21: RU8004.52(2B1) ; also on sheet 26
MCB1_VOUT1_D22: RU8004.50(3B1) ; also on sheet 26
MCB1_VOUT1_D23: RU8004.47(4B1) ; also on sheet 26
MCB2_VIN2A_D0: RU8003.53(1B2) ; also on sheet 27
MCB2_VIN2A_D1: RU8003.51(2B2) ; also on sheet 27
MCB2_VIN2A_D2: RU8003.48(3B2) ; also on sheet 27
MCB2_VIN2A_D3: RU8003.46(4B2) ; also on sheet 27
MCB2_VIN2A_D4: RU8003.44(5B2) ; also on sheet 27
MCB2_VIN2A_D5: RU8003.42(6B2) ; also on sheet 27
MCB2_VIN2A_D6: RU8003.40(7B2) ; also on sheet 27
MCB2_VIN2A_D7: RU8003.37(8B2) ; also on sheet 27
MCB3_GPMC_A0: RU8003.22(9B3) ; also on sheet 9
MCB3_GPMC_A1: RU8003.24(10B3) ; also on sheet 9
MCB3_GPMC_A2: RU8003.26(11B3) ; also on sheet 9
MCB3_GPMC_A3: RU8003.28(12B3) ; also on sheet 9
MCB3_GPMC_A4: RU8004.3(1B3) ; also on sheet 9
MCB3_GPMC_A5: RU8004.5(2B3) ; also on sheet 9
MCB3_GPMC_A6: RU8004.7(3B3) ; also on sheet 9
MCB3_GPMC_A7: RU8004.10(4B3) ; also on sheet 9
MCB3_GPMC_A20: RU8003.3(1B3) ; also on sheet 9
MCB3_GPMC_A21: RU8003.5(2B3) ; also on sheet 9
MCB3_GPMC_A22: RU8003.7(3B3) ; also on sheet 9
MCB3_GPMC_A23: RU8003.10(4B3) ; also on sheet 9
MCB3_GPMC_A24: RU8003.12(5B3) ; also on sheet 9
MCB3_GPMC_A25: RU8003.14(6B3) ; also on sheet 9
MCB3_GPMC_A26: RU8003.16(7B3) ; also on sheet 9
MCB3_GPMC_A27: RU8003.20(8B3) TP8040.1(TP)
MEB2_CPI_FID: TP8054.1(TP) ; also on sheet 34
MEB2_CPI_WEn: TP8052.1(TP) ; also on sheet 34
MJB1_DCAN2_RX: RU8012.34(10B1) ; also on sheet 35
MJB1_DCAN2_TX: RU8012.36(9B1) ; also on sheet 35
MJB1_TIMER1: RU8012.52(2B1) ; also on sheet 21
MJB1_TIMER2: RU8012.50(3B1) ; also on sheet 21
MJB1_TIMER3: RU8012.32(11B1) ; also on sheet 21
MJB1_VIN2A_CLK0: RU8012.54(1B1) ; also on sheet 27
MJB1_VIN2A_HSYNC0: RU8012.47(4B1) ; also on sheet 27
MJB1_VIN2A_VSYNC0: RU8012.45(5B1) ; also on sheet 27
MJB2_GPIO2_19: RU8012.53(1B2) TP8039.1(TP)
MJB2_UART1_CTSn/SPI4_SCLK: RU111.9(3A) RU8012.31(11B2)
MJB2_UART1_RTSn/SPI4_CS0: RU111.12(4A) RU8012.29(12B2)
MJB2_UART1_RXD/SPI4_D1: RU111.4(1A) RU8012.35(9B2)
MJB2_UART1_TXD/SPI4_D0: RU111.7(2A) RU8012.33(10B2)
MJB2_UART2_CTSn: RU8012.46(4B2) ; also on sheet 10
MJB2_UART2_RTSn: RU8012.44(5B2) ; also on sheet 10
MJB2_UART2_RXD: RU8012.51(2B2) ; also on sheet 10
MJB2_UART2_TXD: RU8012.48(3B2) ; also on sheet 10
MJB3_GPMC_A16: RU8012.26(11B3) ; also on sheet 9
MJB3_GPMC_A17: RU8012.28(12B3) ; also on sheet 9
MJB3_GPMC_A18: RU8012.10(4B3) ; also on sheet 9
MJB3_GPMC_A19: RU8012.12(5B3) ; also on sheet 9
MKB1_UART1_CTSn: RU111.11(3B1) ; also on sheet 10
MKB1_UART1_RTSn: RU111.14(4B1) ; also on sheet 10
MKB1_UART1_RXD: RU111.2(1B1) ; also on sheet 10
MKB1_UART1_TXD: RU111.5(2B1) ; also on sheet 10
MKB2_SPI4_CS0: RU111.13(4B2) ; also on sheet 35
MKB2_SPI4_D0: RU111.6(2B2) ; also on sheet 35
MKB2_SPI4_D1: RU111.3(1B2) ; also on sheet 35
MKB2_SPI4_SCLK: RU111.10(3B2) ; also on sheet 35
MMB1_GPIO1_17: RU8015.43(6B1) ; also on sheet 35
MMB1_GPIO1_24: RU8015.39(8B1) TP8055.1(TP)
MMB1_GPIO1_25: RU8015.36(9B1) TP8053.1(TP)
MMB1_GPIO1_26: RU8015.34(10B1) TP8051.1(TP)
MMB1_GPIO1_28: RU8015.32(11B1) TP8050.1(TP)
MMB1_GPIO1_29: RU8015.30(12B1) TP8049.1(TP)
MMB1_RGMII1_RXC: RU8014.30(12B1) ; also on sheet 11
MMB1_RGMII1_RXCTL: RU8014.41(7B1) ; also on sheet 11
MMB1_RGMII1_RXD0: RU8014.32(11B1) ; also on sheet 11
MMB1_RGMII1_RXD1: RU8014.34(10B1) ; also on sheet 11
MMB1_RGMII1_RXD2: RU8014.36(9B1) ; also on sheet 11
MMB1_RGMII1_RXD3: RU8014.39(8B1) ; also on sheet 11
MMB1_RGMII1_TXC: RU8014.54(1B1) ; also on sheet 11
MMB1_RGMII1_TXCTL: RU8014.50(3B1) ; also on sheet 11
MMB1_RGMII1_TXD0: RU8014.43(6B1) ; also on sheet 11
MMB1_RGMII1_TXD1: RU8014.45(5B1) ; also on sheet 11
MMB1_RGMII1_TXD2: RU8014.47(4B1) ; also on sheet 11
MMB1_RGMII1_TXD3: RU8014.52(2B1) ; also on sheet 11
MMB1_SPI3_CS0: R9421.1 RJ20.2 RU8015.47(4B1)
MMB1_SPI3_CS1: RJ19.2 RU8015.45(5B1)
MMB1_SPI3_D0: RJ22.2 RU8015.52(2B1)
MMB1_SPI3_D1: RJ23.2 RU8015.54(1B1)
MMB1_SPI3_SCLK: RJ21.2 RU8015.50(3B1)
MMB3_GPMC_AD00: R110.1 R9264.1 RU8014.22(9B3) SW2.1(A1) ; also on sheet 9
MMB3_GPMC_AD01: R111.1 R9267.1 RU8014.24(10B3) SW2.2(A2) ; also on sheet 9
MMB3_GPMC_AD02: R112.1 R9268.1 RU8014.26(11B3) SW2.3(A3) ; also on sheet 9
MMB3_GPMC_AD03: R113.1 R9262.1 RU8015.14(6B3) SW2.4(A4) ; also on sheet 9
MMB3_GPMC_AD04: R114.1 R9265.1 RU8015.16(7B3) SW2.5(A5) ; also on sheet 9
MMB3_GPMC_AD05: R115.1 R9263.1 RU8015.3(1B3) SW2.6(A6) ; also on sheet 9
MMB3_GPMC_AD06: R116.1 R9261.1 RU8015.5(2B3) SW2.7(A7) ; also on sheet 9
MMB3_GPMC_AD07: RU8015.7(3B3) ; also on sheet 9
MMB3_GPMC_AD08: R118.1 R9272.1 RU8015.10(4B3) SW3.1(A1) ; also on sheet 9
MMB3_GPMC_AD09: R119.1 R9275.1 RU8015.12(5B3) SW3.2(A2) ; also on sheet 9
MMB3_GPMC_AD10: R120.1 R9276.1 RU8015.20(8B3) SW3.3(A3) ; also on sheet 9
MMB3_GPMC_AD11: R121.1 R9270.1 RU8015.22(9B3) SW3.4(A4) ; also on sheet 9
MMB3_GPMC_AD12: R122.1 R9273.1 RU8015.24(10B3) SW3.5(A5) ; also on sheet 9
MMB3_GPMC_AD13: R123.1 R9271.1 RU8014.28(12B3) SW3.6(A6) ; also on sheet 9
MMB3_GPMC_AD14: R124.1 R9269.1 RU8015.26(11B3) SW3.7(A7) ; also on sheet 9
MMB3_GPMC_AD15: R125.1 R9274.1 RU8015.28(12B3) SW3.8(A8) ; also on sheet 9
MMB3_GPMC_ADVn_ALE: RU8014.10(4B3) ; also on sheet 9
MMB3_GPMC_BEN0: RU8014.7(3B3) ; also on sheet 9
MMB3_GPMC_BEN1: RU8014.5(2B3) ; also on sheet 9
MMB3_GPMC_CLK: RU8014.3(1B3) ; also on sheet 9
MMB3_GPMC_CS0: RU8014.16(7B3) ; also on sheet 9
MMB3_GPMC_OEn_REn: RU8014.12(5B3) ; also on sheet 9
MMB3_GPMC_WAIT0: RU8014.20(8B3) ; also on sheet 9
MMB3_GPMC_WEn: RU8014.14(6B3) ; also on sheet 9
MUX_CNTL0: R239.2 R9283.1 SW8001.1(A1) ; also on sheet 8 9 26
nTRST: J17.9(nTRST) R759.2 R760.1
OE_I2C_HPCTOOL: R3210.2 R3212.2 R3214.2 R3215.2 U3204.5(OE)
OE_I2C_HPCTOOL_Exp: R3212.1 U3201.24(P27)
PAB_PWR_ENABLE: J3200.12 Q2015.D R4138.2
PB_ON: R4138.1 R9355.1 ; also on sheet 12
PCF_VPP_ENn: R199.2 RU14.1(OE) ; also on sheet 8
PM1_SCL: J6101.1 R9257.2 R9455.2 R9501.2 RU8016.4(O) U6105.1(IO1) ; also on sheet 37
PM1_SDA: J6101.2 R9258.2 R9456.2 R9502.2 RU8017.4(O) U6105.3(IO2) ; also on sheet 37
PM2_SCL: J6101.5 R9259.2 R9453.2 R9503.2 RU8018.4(O) U6105.4(IO3) ; also on sheet 15
PM2_SDA: J6101.4 R9260.2 R9454.2 R9504.2 RU8019.4(O) U6105.5(IO4) ; also on sheet 15
PWR_STDBY_HPCTOOL: J3200.10 R9354.1
R_GPMC_AD00/RGMII1_RXD2/GPIO1_14/SYSBOOT0: RU8014.21(9A) ; also on sheet 7
R_GPMC_AD01/RGMII1_RXD1/GPIO1_15/SYSBOOT1: RU8014.23(10A) ; also on sheet 7
R_GPMC_AD02/RGMII1_RXD0/GPIO1_16/SYSBOOT2: RU8014.25(11A) ; also on sheet 7
R_GPMC_AD03/QSPI1_RTCLK/GPIO1_17/SYSBOOT3: RU8015.13(6A) ; also on sheet 7
R_GPMC_AD04/CAM_STROBE/GPIO1_18/SYSBOOT4: RU8015.15(7A) ; also on sheet 7
R_GPMC_AD05/UART2_TXD/TIMER6/SPI3_D1/GPIO1_19/SYSBOOT5: RU8015.2(1A) ; also on sheet 7
R_GPMC_AD06/UART2_RXD/TIMER5/SPI3_D0/GPIO1_20/SYSBOOT6: RU8015.4(2A) ; also on sheet 7
R_GPMC_AD07/CAM_SHUTTER/TIMER4/SPI3_SCLK/GPIO1_21: RU8015.6(3A) ; also on sheet 7
R_GPMC_AD08/TIMER7/SPI3_CS0/GPIO1_22/SYSBOOT8: RU8015.9(4A) ; also on sheet 7
R_GPMC_AD09/eCAP1_IN_PWM1_OUT/SPI3_CS1/GPIO1_23/SYSBOOT9: RU8015.11(5A) ; also on sheet 7
R_GPMC_AD10/TIMER2/GPIO1_24/SYSBOOT10: RU8015.18(8A) ; also on sheet 7
R_GPMC_AD11/TIMER3/GPIO1_25/SYSBOOT11: RU8015.21(9A) ; also on sheet 7
R_GPMC_AD12/GPIO1_26/SYSBOOT12: RU8015.23(10A) ; also on sheet 7
R_GPMC_AD13/RGMII1_RXC/GPIO1_27/SYSBOOT1: RU8014.27(12A) ; also on sheet 7
R_GPMC_AD14/SPI2_CS1/GPIO1_28/SYSBOOT14: RU8015.25(11A) ; also on sheet 7
R_GPMC_AD15/SPI2_CS0/GPIO1_29/SYSBOOT15: RU8015.27(12A) ; also on sheet 7
R_GPMC_ADVn_ALE/RGMII1_TXD2/EHRPWM1_TRIPZONE_INPUT/CLKOUT1/DMA_EVT4/GPIO1_3: RU8014.9(4A) ; also on sheet 7
R_GPMC_BEN0/RGMII1_TXCTL/EHRPWM1A/DMA_EVT2/GPIO1_1: RU8014.6(3A) ; also on sheet 7
R_GPMC_BEN1/RGMII1_TXD3/EHRPWM1B/DMA_EVT3/GPIO1_2: RU8014.4(2A) ; also on sheet 7
R_GPMC_CLK/RGMII1_TXC/CLKOUT0/DMA_EVT1/GPIO1_0: RU8014.2(1A) ; also on sheet 7
R_GPMC_CS0/RGMII1_RXCTL/GPIO1_6: RU8014.15(7A) ; also on sheet 7
R_GPMC_CS1/QSPI1_CS0/GPIO1_7: RJ13.2 ; also on sheet 7
R_GPMC_CS2/QSPI1_D3/GPIO1_8: RJ14.2 ; also on sheet 7
R_GPMC_CS3/QSPI1_D2/GPIO1_9: RJ15.2 ; also on sheet 7
R_GPMC_CS4/QSPI1_D0/GPIO1_10: RJ16.2 ; also on sheet 7
R_GPMC_CS5/QSPI1_D1/GPIO1_11: RJ17.2 ; also on sheet 7
R_GPMC_CS6/QSPI1_SCLK/GPIO1_12: RJ18.2 ; also on sheet 7
R_GPMC_OEn_REn/RGMII1_TXD1/EHRPWM_SYNCI/CLKOUT2/GPIO1_4: RU8014.11(5A) ; also on sheet 7
R_GPMC_WAIT0/RGMII1_RXD3/QSPI1_RTCLK/DMA_EVT4/GPIO1_13: RU8014.18(8A) ; also on sheet 7
R_GPMC_WEn/RGMII1_TXD0/EHRPWM_SYNCO/GPIO1_5: RU8014.13(6A) ; also on sheet 7
R_I2C1_SCL: R9279.2 R9455.1 ; also on sheet 7 8 13 36
R_I2C1_SDA: R9278.2 R9456.1 ; also on sheet 7 8 13 36
R_I2C2_SCL: R9453.1 ; also on sheet 7
R_I2C2_SDA: R9454.1 ; also on sheet 7
R_UART1_CTSn/XREF_CLK1/UART3_RXD/GPMC_A16/SPI4_SCLK/SPI1_CS2/TIMER3/EHRPWM1_SYNCI: RU8012.25(11A) ; also on sheet 7
R_UART1_RTSn/UART3_TXD/GPMC_A17/SPI4_CS0/SPI1_CS3/TIMER4/EHRPWM1_SYNCO: RU8012.27(12A) ; also on sheet 7
R_UART1_RXD/SPI4_D1/QSPI1_RTCLK/GPMC_A12/GPMC_A12/DCAN2_TX/GPIO4_13: RU8012.21(9A) ; also on sheet 7
R_UART1_TXD/SPI4_D0/GPMC_A13/GPMC_A13/DCAN2_RX/GPIO4_1: RU8012.23(10A) ; also on sheet 7
R_UART2_CTSn/XREF_CLK1/GPMC_A18/SPI3_SCLK/QSPI_CS1/TIMER7/VIN2B_D6/VIN2A_HSYNC0/GPMC_CLK: RU8012.9(4A) ; also on sheet 7
R_UART2_RXD/SPI3_D1/QSPI1_RTCLK/GPMC_A12/TIMER1/EHRPWM1A/GPMC_CLK/GPMC_A12/DCAN1_TX/GPIO4_17: RU8012.4(2A) ; also on sheet 7
R_UART2_TXD/SPI3_D0/TIMER2/EHRPWM1B/GPMC_A13/DCAN1_RX/GPIO4_18: RU8012.6(3A) ; also on sheet 7
R_VIN2A_CLK0/GPIO2_19: RU8012.2(1A) ; also on sheet 7
R_VOUT1_CLK/VIN1A_D12/CLKOUT0/VIN2A_CLK0/GPIO2_20: RU8002.9(4A) ; also on sheet 7
R_VOUT1_D00/MCASP1_AXR0/VIN1A_D17/MMC_CLK/GPIO2_25: RU8002.11(5A) ; also on sheet 7
R_VOUT1_D01/MCASP1_AXR1/VIN1A_D18/MMC_CMD/GPIO2_26: RU8002.13(6A) ; also on sheet 7
R_VOUT1_D02/MCASP1_AXR2/VIN1A_D19/MCASP1_AXR8/MMC_DAT0/OBS0/OBS16/OBS_IRQ1/GPIO2_27: RU8002.15(7A) ; also on sheet 7
R_VOUT1_D03/MCASP1_AXR3/VIN1A_D20/MCASP1_AXR9/MMC_DAT1/OBS1/OBS17/OBS_DMARQ1/GPIO2_28: RU8002.18(8A) ; also on sheet 7
R_VOUT1_D04/MCASP1_AXR4/VIN1A_D21/MCASP1_AXR10/MMC_DAT2/OBS2/OBS18/GPIO2_29: RU8002.21(9A) ; also on sheet 7
R_VOUT1_D05/MCASP1_AXR5/VIN1A_D22/MCASP1_AXR11/MMC_DAT3/OBS3/OBS19/VIN2A_CLK0/GPIO2_30: RU8002.23(10A) ; also on sheet 7
R_VOUT1_D06/MCASP1_AXR6/VIN1A_D23/MCASP1_AXR12/ESM_ERROR/OBS4/OBS20/VIN2A_DE0/GPIO2_31: J17.13(TR_CLK0) RU8002.25(11A) ; also on sheet 7
R_VOUT1_D07/MCASP1_AXR7/eCAP1_IN_PWM1_OUT/MCASP1_AXR13/EMU3/VIN2A_FLD0/GPIO3_0: J17.17(TRD0.0) RU8002.27(12A) ; also on sheet 7
R_VOUT1_D08/MCASP1_AXR8/VIN2A_D0/GPMC_A20/EMU4/GPIO3_1: J17.23(TRD0.3) RU8003.2(1A) ; also on sheet 7
R_VOUT1_D09/MCASP1_AXR9/VIN2A_D1/GPMC_A21/EMU5/GPIO3_2: J17.25(TRD0.4) RU8003.4(2A) ; also on sheet 7
R_VOUT1_D10/MCASP1_AXR10/VIN2A_D2/GPMC_A22/EMU6/OBS5/OBS21/OBS_IRQ2/GPIO3_3: J17.27(TRD0.5) RU8003.6(3A) ; also on sheet 7
R_VOUT1_D11/MCASP1_AXR11/VIN2A_D3/GPMC_A23/EMU7/OBS6/OBS22/OBS_DMARQ2/GPIO3_: J17.29(TRD0.6) RU8003.9(4A) ; also on sheet 7
R_VOUT1_D12/MCASP1_AXR12/VIN2A_D4/GPMC_A24/EMU8/OBS7/OBS23/GPIO3_5: J17.31(TRD0.7) RU8003.11(5A) ; also on sheet 7
R_VOUT1_D13/MCASP1_AXR13/VIN2A_D5/GPMC_A25/EMU9/OBS8/OBS24/GPIO3_6: J17.33(TRD0.8) RU8003.13(6A) ; also on sheet 7
R_VOUT1_D14/MCASP1_AXR14/VIN2A_D6/GPMC_A26/EMU10/OBS9/OBS25/GPIO3_7: J17.35(TRD0.9) RU8003.15(7A) ; also on sheet 7
R_VOUT1_D15/MCASP1_AXR15/VIN2A_D7/GPMC_A27/EMU11/OBS10/OBS26/GPIO3_: J17.37(TRD3.0) RU8003.18(8A) ; also on sheet 7
R_VOUT1_D16/MCASP1_AHCLKX/VIN2A_D8/GPMC_A0/MCASP1_ARX8/VIN2B_D0/EMU12/GPIO3_9: J17.39(TRD3.1) RU8003.21(9A) ; also on sheet 7
R_VOUT1_D17/VIN2A_D9/GPMC_A1/MCASP1_ARX9/VIN2B_D1/EMU13/GPIO3_10: J17.41(TRD3.2) RU8003.23(10A) ; also on sheet 7
R_VOUT1_D18/VIN2A_D10/GPMC_A2/MCASP1_AXR10/VIN2B_D2/EMU14/OBS11/OBS27/GPIO3_1: J17.43(TRD3.3) RU8003.25(11A) ; also on sheet 7
R_VOUT1_D19/VIN2A_D11/GPMC_A3/MCASP1_AXR11/VIN2B_D3/EMU15/OBS12/OBS28/GPIO3_12: J17.45(TRD3.4) RU8003.27(12A) ; also on sheet 7
R_VOUT1_D20/VIN2A_D12/GPMC_A4/MCASP1_AXR12/VIN2B_D4/EMU16/OBS13/OBS29/GPIO3_13: J17.47(TRD3.5) RU8004.2(1A) ; also on sheet 7
R_VOUT1_D21/VIN2A_D13/GPMC_A5/MCASP1_AXR13/VIN2B_D5/EMU17/OBS14/OBS30/GPIO3_14: J17.49(TRD3.6) RU8004.4(2A) ; also on sheet 7
R_VOUT1_D22/VIN2A_D14/GPMC_A6/MCASP1_AXR14/VIN2B_D6/EMU18/OBS15/OBS31/GPIO3_15: J17.51(TRD3.7) RU8004.6(3A) ; also on sheet 7
R_VOUT1_D23/VIN2A_D15/GPMC_A7/MCASP1_AXR15/VIN2B_D7/EMU19/GPIO3_16: J17.53(TRD3.8) RU8004.9(4A) ; also on sheet 7
R_VOUT1_DE/MCASP1_ACLKX/VIN1A_D13/CLKOUT1/GPIO2_21: RU8002.6(3A) ; also on sheet 7
R_VOUT1_HSYNC/MCASP1_ACLKR//VIN1A_D15/VIN2A_DE0/GPIO2_23: RU8002.4(2A) ; also on sheet 7
R_VOUT1_VSYNC/MCASP1_FSR//VIN1A_D16/VIN2A_FLD0/GPIO2_24: RU8002.2(1A) ; also on sheet 7
RMB1_SPI3_CS0: RJ20.1 ; also on sheet 20
RMB1_SPI3_CS1: RJ19.1 ; also on sheet 22
RMB1_SPI3_MISO: RJ23.1 ; also on sheet 20
RMB1_SPI3_MOSI: RJ22.1 ; also on sheet 20 22
RMB1_SPI3_SCLK: RJ21.1 ; also on sheet 20 22
RMB2_SPI3_CS0: RJ20.3 ; also on sheet 35
RMB2_SPI3_CS1: RJ19.3 ; also on sheet 35
RMB2_SPI3_D0: RJ22.3 ; also on sheet 35
RMB2_SPI3_D1: RJ23.3 ; also on sheet 35
RMB2_SPI3_SCLK: RJ21.3 ; also on sheet 35
RMB3_TIMER7: R9421.2 ; also on sheet 21
RNB1_QSPI1_CS0: RJ13.1 ; also on sheet 9
RNB1_QSPI1_D0: RJ16.1 ; also on sheet 9
RNB1_QSPI1_D1: RJ17.1 ; also on sheet 9
RNB1_QSPI1_D2: RJ15.1 ; also on sheet 9
RNB1_QSPI1_D3: RJ14.1 ; also on sheet 9
RNB1_QSPI1_SCLK: RJ18.1 ; also on sheet 9
RNB2_GPMC_CS1: RJ13.3 ; also on sheet 9
RNB2_GPMC_CS2: RJ14.3 ; also on sheet 9
RNB2_GPMC_CS3: RJ15.3 ; also on sheet 9
RNB2_GPMC_CS4: RJ16.3 ; also on sheet 9
RNB2_GPMC_CS5: RJ17.3 ; also on sheet 9
RNB2_GPMC_CS6: RJ18.3 ; also on sheet 9
SEL_HDMI_INn: SW8001.8(A8) ; also on sheet 8 23 25
SEL_MA0: RU8002.1(S0) ; also on sheet 26
SEL_MA1: RU8002.56(S1) ; also on sheet 26
SEL_MC0: RU8003.1(S0) RU8004.1(S0) ; also on sheet 26
SEL_MC1: RU8003.56(S1) RU8004.56(S1) ; also on sheet 26
SEL_MJ0: RU8012.1(S0) ; also on sheet 26
SEL_MJ1: RU8012.56(S1) ; also on sheet 26
SEL_MK0: RU111.1(S) ; also on sheet 26
SEL_MM0: RU8014.1(S0) RU8015.1(S0) ; also on sheet 26
SEL_MM1: RU8014.56(S1) RU8015.56(S1) ; also on sheet 26
SPARE_GPIO_2: J3200.14 R3210.1
SPARE_PW: J3200.8 R3208.1
SPI2_D0/UART3_RTSn/TIMER1/GPIO4_7/SYSBOOT7: R117.1 R9266.1 SW2.8(A8) ; also on sheet 7 35 36
SW_VPP_EN: RU14.2(I) SW8001.7(A7)
TRSTPD: J17.8(TRSTPD) R700.1 R761.1
V_2V5_Board_Detect: C3204.2 C3207.1 C3208.2 J3200.1 J3200.2 R3202.2 R3203.2 R3204.2 R3205.2 R3219.2 R4135.2 R4136.2 U3201.31(VCCI) U3203.5(OUT) U3204.8(VCCB)
V_3V3_HPCTOOL: C3205.1 R3208.2 R3209.1 R3211.1 R3213.2 R3218.2 U3202.5(OUT)
VBUCK_3V3: R1005.2 R1006.2 R1007.1 R1008.1 R9501.1 R9502.1 R9503.1 R9504.1 ; also on sheet 12 15 37
VLIM_12V: C3200.2 C3206.2 R4139.2 R9353.2 U3202.1(IN) U3203.1(IN) ; also on sheet 12 37
VOUT_I2C_SCL: U8029.2(A0) ; also on sheet 7 16 17
VOUT_I2C_SCL_3V3: R9371.2 U8029.7(B0) ; also on sheet 18
VOUT_I2C_SDA: U8029.3(A1) ; also on sheet 7 16 17
VOUT_I2C_SDA_3V3: R9372.2 U8029.6(B1) ; also on sheet 18
VPM_1V8: C6107.1 C6109.1 C6116.1 C6117.1 U6103.12(VCORE) U6103.37(VCORE) U6103.49(VREGOUT) U6103.64(VCORE)
VPM_3V3: C6100.1 C6105.1 C6108.1 C6110.1 C6113.1 C6118.1 C6119.1 C8254.2 C8255.2 L6100.2 L6101.2 R6100.2 R6102.2 R6103.2 R6107.1 RJ1405.1 RJ1406.1 RU8016.5(VCC) RU8017.5(VCC) RU8018.5(VCC) RU8019.5(VCC) U6100.1(VOUT) U6101.6(VCC) U6103.20(VCCIO) U6103.31(VCCIO) U6103.42(VCCIO) U6103.50(VREGIN) U6103.56(VCCIO)
VPM_VBUS: C6103.1 C6104.1 J6100.1(USBVDD) R6101.1 U6100.4(EN) U6100.6(VIN) U6102.1(VCC)
VPP_EN: RU14.4(O) ; also on sheet 5
VPRH_3V3: C403.2 C8155.2 C8157.2 R199.1 R594.1 R9371.1 R9372.1 R9373.1 R9374.1 RU14.5(VCC) RU8002.55(S2) RU8003.55(S2) RU8004.55(S2) RU8012.55(S2) RU8014.55(S2) RU8015.55(S2) U8028.8(VCCB) U8029.8(VCCB) ; also on sheet 8 9 11 15 16 17 18 19 20 21 22 23 25 34 35
VPRH_DV: C3201.2 C3209.2 C8154.1 C8156.1 R80.1 R81.1 R82.1 R83.1 R84.1 R85.1 R86.1 R87.1 R88.1 R89.1 R90.1 R91.1 R92.1 R93.1 R94.1 R95.1 R234.1 R239.1 R383.1 R459.1 R470.1 R698.1 R703.1 R704.1 R758.1 R759.1 R766.1 R3215.1 R9369.1 R9370.1 R9487.1 U3201.27(VCCP) U3204.1(VCCA) U8028.1(VCCA) U8029.1(VCCA) ; also on sheet 4 7 8 9 10 11 13 15 16 17 18 19 20 21 22 23 26 27 35 36
VREF_JTAG: J17.1(VREF_DBG) J17.12(VREF_TR) R758.2
VSYS_3V3: C8066.1 RU111.16(VCC) ; also on sheet 6 12 13 14 16 26 27 37
VSYS_5V0: C8054.1 C8055.1 C8058.1 C8064.1 C8067.1 C8068.1 RU8002.17(VCC.1) RU8003.17(VCC.1) RU8004.17(VCC.1) RU8012.17(VCC.1) RU8014.17(VCC.1) RU8015.17(VCC.1) ; also on sheet 14 34 37
VSYS_12V: R9357.2 R9358.2 ; also on sheet 12 37
N19240062: R85.2 SW2.11(B6)
N19240090: R86.2 SW2.10(B7)
N19240118: R87.2 SW2.9(B8)
N19692324: R80.2 SW2.16(B1)
N19692326: R81.2 SW2.15(B2)
N19692328: R82.2 SW2.14(B3)
N19692409: R83.2 SW2.13(B4)
N19692411: R84.2 SW2.12(B5)
N24608703: R3218.1 R3220.2 U3202.4(FB)
N24608707: R3219.1 R3221.2 U3203.4(FB)
N24609498: J3200.15 R3211.2
N24609528: J3200.7 R3207.2 R3217.1
N24611921: R4135.1 U3201.32(~{INT})
N24611926: R4136.1 U3201.28(~{RESET})
N24629946: R6102.1 U6101.5(CS) U6103.63(EECS)
N24629990: C6111.1 C6112.1 L6100.1 U6103.4(VPHY)
N24630010: R6104.2 U6101.3(DIN) U6103.61(EEDATA)
N24630186: R6103.1 R6104.1 U6101.1(DO)
N24630450: C6114.1 C6115.1 L6101.1 U6103.9(VPLL)
N24630454: D6100.2(C) U6103.60(PWREN#)
N24630456: J6100.3(D+) U6102.3(IO1) U6103.8(USBDP)
N24630458: R6100.1 U6101.4(CLK) U6103.62(EESK)
N24630464: C6102.1 U6100.2(NR)
N24630500: R6107.2 U6103.14(RESET#)
N24630508: J6100.2(D-) U6102.5(IO2) U6103.7(USBDM)
N24630540: C6101.1 U6103.2(OSCI) Y6100.1
N24630543: C6106.1 U6103.3(OSCO) Y6100.3
N24630552: J6100.6(SHIELD1) J6100.7(SHIELD2) J6100.8(SHIELD3) J6100.9(SHIELD4) R6106.1
N24632385: R1006.1 R6108.2 U6103.16(ADBUS0/TXD/TCK)
N24632388: R1005.1 R6109.2 U6103.17(ADBUS1/RXD/TDI)
N24632391: R6110.2 U6103.18(ADBUS2/RTS#/TDO)
N24632394: R1008.2 R6111.2 U6103.38(BDBUS0/TXD/TCK)
N24632397: R1007.2 R6112.2 U6103.39(BDBUS1/RXD/TDI)
N24632400: R6113.2 U6103.40(BDBUS2/RTS#/TDO)
N24632476: R6109.1 R6110.1 RU8017.2(I)
N24632500: R6112.1 R6113.1 RU8019.2(I)
N25226266: RU8002.29(12B2) TP8003.1(TP)
N26154894: R594.2 SW8001.10(B7)
N26154906: R599.2 SW8001.11(B6)
N26154912: R604.2 SW8001.13(B4)
N26154926: R601.2 SW8001.12(B5)
N26154936: R585.2 SW8001.9(B8)
N26155028: R612.2 SW8001.15(B2)
N26155030: R619.2 SW8001.16(B1)
N26155032: R610.2 SW8001.14(B3)
N26380816: R9279.1 U3204.2(A0)
N26380819: R9278.1 U3204.3(A1)
N26381075: R9282.2 U6103.24(ADBUS7/RI#/GPIOL3)
N26741202: Q2015.G Q2024.3(D) R9353.1
N26741639: Q2024.1(G) R4139.1 R9352.1 R9354.2
N26741900: Q2026.D R9355.2
N26741955: Q2025.3(D) Q2026.G R9358.1
N26741961: Q2025.1(G) R9282.1 R9356.1 R9357.1
N27521606: J17.15(TGT_DETECT) R762.2
N27522113: R9199.1 SW8.4(A4)
N27522117: R9200.1 SW8.3(A3)
N27832684: R9369.2 U8028.5(OE)
N27832772: R9370.2 U8029.5(OE)
N30079472: R88.2 SW3.16(B1)
N30079474: R89.2 SW3.15(B2)
N30136938: R90.2 SW3.14(B3)
N30136939: R91.2 SW3.13(B4)
N30139026: R92.2 SW3.12(B5)
N30139028: R93.2 SW3.11(B6)
N30141933: R94.2 SW3.10(B7)
N30141935: R95.2 SW3.9(B8)
N30748802: RJ1405.2 RU8016.1(OE) RU8017.1(OE) U6103.23(ADBUS6/DCD#/GPIOL2)
N30748986: R6108.1 RU8016.2(I)
N30749228: RJ1406.2 RU8018.1(OE) RU8019.1(OE) U6103.45(BDBUS6/DCD#/GPIOL2)
N30749632: R6111.1 RU8018.2(I)
N30949723: D6100.1(A) R6101.2
N30949724: R6105.2 U6103.6(REF)

Not connected (* = marked no-connect by the designer): J17 10(EXTE)* 11(EXTF)* 14(TR_CLK1)* 18(TRD1.0)* 20(TRD1.1)* 22(TRD1.2)* 24(TRD1.3)* 26(TRD1.4)* 28(TRD1.5)* 30(TRD1.6)* 32(TRD1.7)* 34(TRD1.8)* 36(TRD1.9)* 38(TRD2.0)* 40(TRD2.1)* 42(TRD2.2)* 44(TRD2.3)* 46(TRD2.4)* 48(TRD2.5)* 50(TRD2.6)* 52(TRD2.7)* 54(TRD2.8)* 55(TRD3.9)* 56(TRD2.9)* 59(TR_CLK3)* 60(TR_CLK2)*; J3200 11 13 16 17 19 21 23; J6100 4(ID)*; RU8002 3(1B3) 5(2B3) 7(3B3) 10(4B3) 12(5B3) 14(6B3) 16(7B3) 20(8B3) 22(9B3) 24(10B3) 26(11B3) 28(12B3) 46(4B2) 48(3B2) 51(2B2); RU8004 11(5A) 12(5B3) 13(6A) 14(6B3) 15(7A) 16(7B3) 18(8A) 20(8B3) 21(9A) 22(9B3) 23(10A) 24(10B3) 25(11A) 26(11B3) 27(12A) 28(12B3) 29(12B2) 30(12B1) 31(11B2) 32(11B1) 33(10B2) 34(10B1) 35(9B2) 36(9B1) 37(8B2) 39(8B1) 40(7B2) 41(7B1) 42(6B2) 43(6B1) 44(5B2) 45(5B1); RU8012 3(1B3) 5(2B3) 7(3B3) 13(6A) 14(6B3) 15(7A) 16(7B3) 18(8A) 20(8B3) 22(9B3) 24(10B3) 30(12B1) 37(8B2) 39(8B1) 40(7B2) 41(7B1) 42(6B2) 43(6B1); RU8014 29(12B2) 31(11B2) 33(10B2) 35(9B2) 37(8B2) 40(7B2) 42(6B2) 44(5B2) 46(4B2) 48(3B2) 51(2B2) 53(1B2); RU8015 29(12B2) 31(11B2) 33(10B2) 35(9B2) 37(8B2) 40(7B2) 42(6B2) 44(5B2) 46(4B2) 48(3B2) 51(2B2) 53(1B2); U3201 18(P21) 19(P22) 20(P23) 21(P24) 22(P25) 23(P26); U6100 5(NC); U6102 2(NC)*; U6103 19(ADBUS3/CTS#/TMS) 21(ADBUS4/DTR#/GPIOL0) 22(ADBUS5/DSR#/GPIOL1) 26(ACBUS0/TXDEN/GPIOH0) 27(ACBUS1/WRSTB#/GPIOH1) 28(ACBUS2/RDSTB#/GPIOH2) 29(ACBUS3/RXLED#/GPIOH3) 30(ACBUS4/TXLED#/GPIOH4) 32(ACBUS5/-/GPIOH5) 33(ACBUS6/-/GPIOH6) 34(ACBUS7/-/GPIOH7) 36(SUSPEND#) 41(BDBUS3/CTS#/TMS) 43(BDBUS4/DTR#/GPIOL0) 44(BDBUS5/DSR#/GPIOL1) 46(BDBUS7/RI#/GPIOL3) 48(BCBUS0/TXDEN/GPIOH0) 52(BCBUS1/WRSTB#/GPIOH1) 53(BCBUS2/RDSTB#/GPIOH2) 54(BCBUS3/RXLED#/GPIOH3) 55(BCBUS4/TXLED#/GPIOH4) 57(BCBUS5/-/GPIOH5) 58(BCBUS6/-/GPIOH6) 59(BCBUS7/-/GPIOH7)

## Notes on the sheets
sheet 28
- V_3V3_HPCTOOL
- 2V5 HPCTOOL
- 100mA max
- 100mA max
- HPCTOOL
- (PAB/nTEB)
- FPGA_nCONFIG
- LOW TO TURN POWER OFF
- PB_ON LOGIC IS ALL REFERENCED TO VLIM_12V
  SO THE FETS PROVIDE TRANSLATION AND POWER
  ON BY DEFAULT WITH NO HPC-TOOL IS CONNECTED.
- ON(DEFAULT)- Q2024-G HIGH, Q2015-G LOW,
  PB_ON HIGH SYSTEM POWER ON.
- OFF - Q2024-G LOW, Q2015-G HIGH,
  PB_ON LOW SYSTEM POWER OFF.
sheet 29
- ER41
- ER52
- ER41
- ER41
- Digikey no: XC1118CT-ND
  Manufactor no: ECS-120-20-30B-TR
- LOW TO TURN POWER OFF
sheet 30
- Board Mux A
- TDA3x
- VOUT CPLD
- VIP CPLD
- (open)
- Board Mux B
- MUX A/C
- PANEL
- FPD-LINK
- HDMI
- (Implemented in VOUT CPLD)
- Board Mux C
- TDA3x
- VOUT CPLD
- VIP CPLD
- GPMC NOR/EXP
sheet 31
- SYSBOOT Control
- Note: Switch OFF is logic '0', ON is logic '1'.
- [SYSBOOT0]
- [SYSBOOT1]
- [SYSBOOT2]
- [SYSBOOT3]
- [SYSBOOT4]
- [SYSBOOT5]
- [SYSBOOT6]
- [SYSBOOT7]
- Silkscreen: SYSBOOT[7:0]
- [SYSBOOT8]
- [SYSBOOT9]
- PLACE THESE RESISTORS NEAR THE
  BOOT SWITCHES.  NO-POP TO REMOVE HPC
  STUBS. THESE Rs NEED TO BE 1K OR HIGHER.  THE
  I2C EXPANDER IS A FET TO VCC RAIL AND OR GROUND.
- [SYSBOOT10]
- [SYSBOOT11]
- [SYSBOOT12]
- [SYSBOOT13]
- [SYSBOOT14]
- [SYSBOOT15]
- Silkscreen: SYSBOOT[15:8]
- Board Configuration
- Note: Switch OFF is logic '0', ON is logic '1'.
- [SEL_GPMCn]
- [EEPROM_WP]
- [USR_SW1]
- [USR_SW2]
- [USR_SW3]
- [USR_SW4]
- [SEL_9127n]
- ER43
- Silkscreen: BRD_CONFIG
- MIPI-60 JTAG/Emulation Interface
- [EMU2]
- ER43
- [EMU3]
- [EMU0]
- [EMU1]
- [EMU4]
- [EMU5]
- [EMU6]
- [EMU7]
- [EMU8]
- [EMU9]
- Note: FOR CJTAG REMOVE R761 AND POPULATE R760,
  AS CTJAG NEEDS THE PULLUP VERSION.
  TRSTn ==  MIPI TRSTPD PULL DOWN VERSION
  TRSTn ==  MIPI nTRST MIPI PULLUP VERSION
- [EMU10]
- [EMU11]
- [EMU12]
- [EMU13]
- [EMU14]
- [EMU15]
- [EMU16]
- [EMU17]
- [EMU18]
- [EMU19]
sheet 32
- Board Mux J
- TDA3x
- DCAN/VIP CPLD
- MUX J
- GPMC
- Board Mux K
- MUX J
- TERMINAL
- SPI EXP
- Note:  UART1_RTS signal is R-Mux with QSPI RTCLK, and is not available by default.
- ER8, ER9
- Board Mux M
- Board Mux N
- TDA3x
- RGMII1 EXP / SPI3 / GPIO
- TDA3x
- QSPI MEMORY
- (open)
- GPMC NOR/EXP
- GPMC
- Board Mux M
- MUX M
- SAFETY MCU
- SPI EXP
sheet 33
- SVB COMPONENTS NOT
  POPULATED ON EVM
- SN74CBT16214DGGR MAPPING
- SH05 - SOC 2
  J6116
  J6117
  J6118
  J6107
  J76
  J6102
  J83
  SH08 - VISIBILITY
  J1003
  J28
  SH09 - BOOT/JTAG
  R9261
  R9262
  R9263
  R9264
  R9265
  R9266
  R9267
  R9268
  R9269
  R9270
  R9271
  R9272
  R9273
  R9274
  R9275
  R9276
  R9283
  R9199
  R9200
  SW8
  SH15 - MEM NONVOLATILE
  J40
  Xu83 (socket)
  SH17 - CAN/SAFETY MCU
  J6108
  J6110
  J6109
  J6106
  SH23 - POWER BENCH/MONITORS
  J78
  J6103
  J6104
  J6105
  SH36 - TOOL HPC
  C3200
  C3201
  C3204
  C3205
  C3206
  C3207
  C3208
  C3209
  J3200
  Q2015
  Q2024
  R3202
  R3203
  R3204
  R3205
  R3207
  R3208
  R3209
  R3210
  R3211
  R3212
  R3213
  R3214
  R3215
  R3216
  R3217
  R3218
  R3219
  R3220
  R3221
  R4135
  R4136
  R4138
  R4139
  R9278
  R9279
  R9352
  R9353
  R9354
  U3201
  U3202
  U3203
  U3204
- CAPACITOR SIZING FOR COMMERCIAL vs AUTOMOTIVE
- CAPACITANCE      Commerical     Automotive
  Vaule            Size/X5R       Size/X7R
  .1uF             0201           0402
  .22uF            0201           0603
  .47uF            0201           0603
  1uF              0201           0603
  2.2uF            0402           0603
  4.7uF            0402           0805
  10uF             0402           0805
  22uF             0603           1206
- DDR3 DEVICE OPTIONS
- MT41K128M16JT-125 M:K  0-95C
  MT41K128M16JT-125 IT:K -40-95C
  MT41K128M16JT-125 AAT:K -40-105C
- SINGLE NET NODES AVAILABLE FOR TEST POINTS
- Sync w/ schematic from April 2
